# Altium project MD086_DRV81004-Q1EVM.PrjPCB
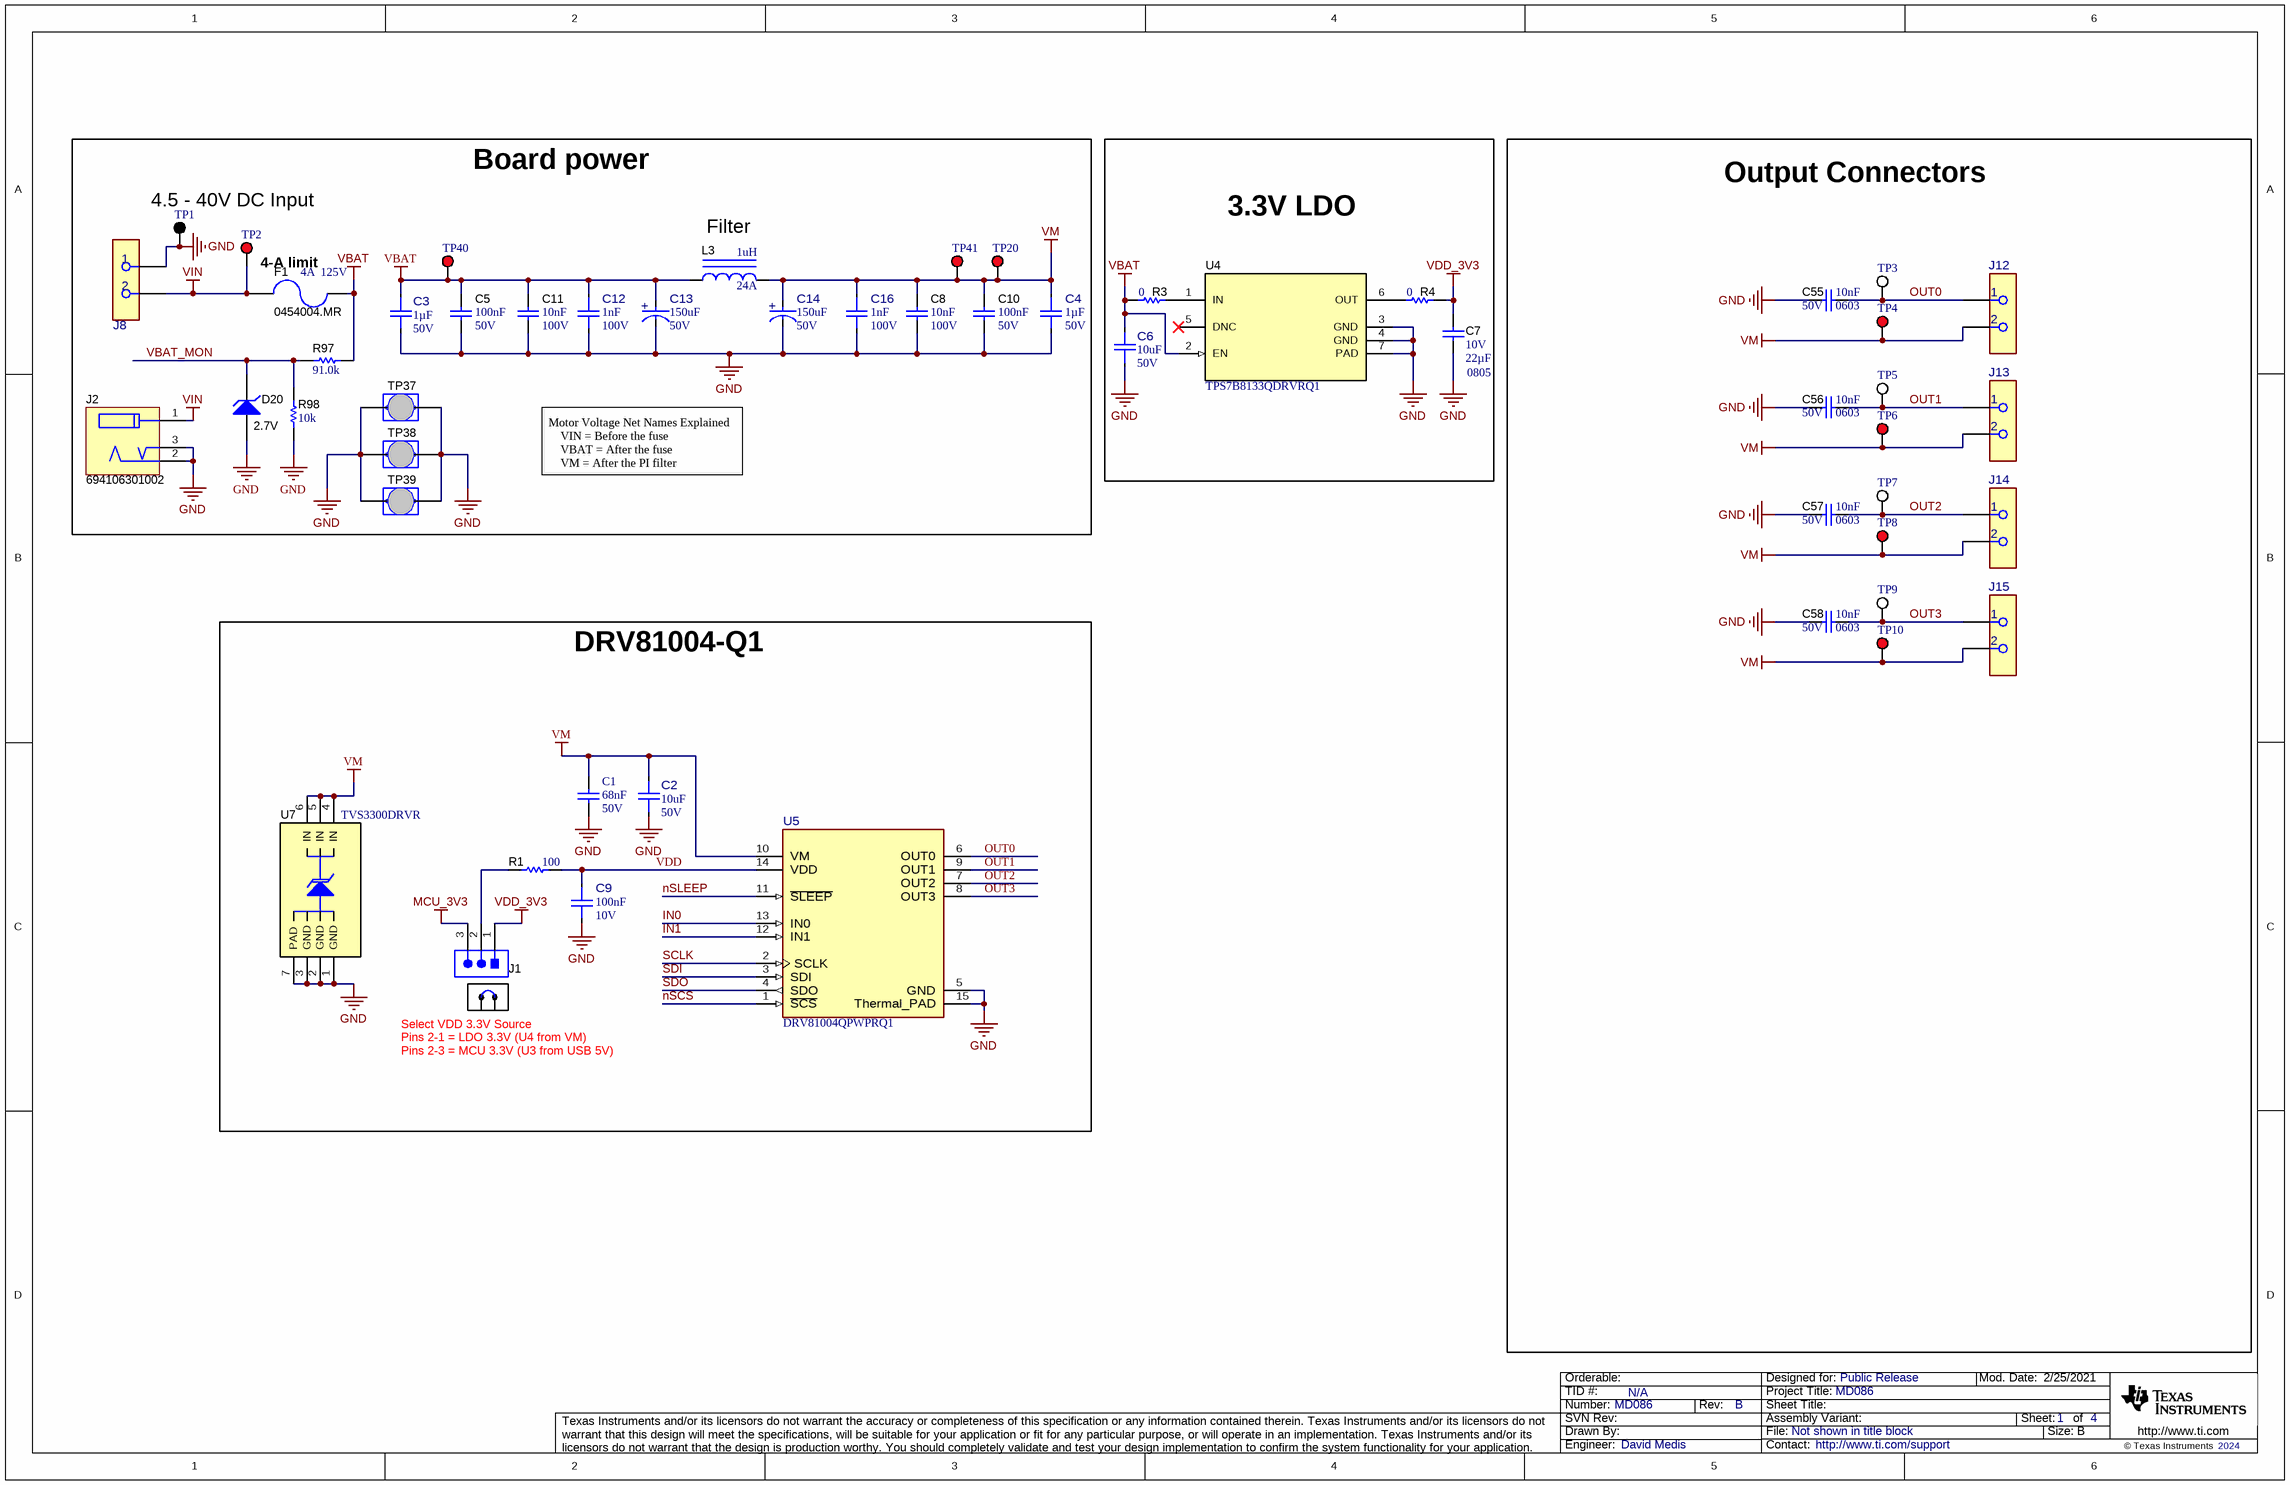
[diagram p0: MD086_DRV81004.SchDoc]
TID: N/A; TechSupport: http://www.ti.com/support; SCH_Rev: B; PRJ_Title: MD086; PRJ_Num_and_Rev: MD086B; PRJ_Number: MD086; PRJ_Engineer: David Medis; PRJ_Customer: Public Release; PCB_Rev: B; PCB_Layout: Jacob Thompson; DRV_PartNumber: DRV81004-Q1; DRV_EVM_Orderable: DRV81004-Q1EVM; CopyrightYear: 2024
4 sheets, 217 parts. Net scope: global (net labels, ports and power ports of the same name join across sheets).
Board file: DRV81004-Q1EVM.PcbDoc
Sheets:
  MD086_DRV81004.SchDoc
  MD086_ezFET.SchDoc
  MD086_MCU.SchDoc
  MD086_Hardware.SchDoc

## Sheet MD086_DRV81004.SchDoc
size 431 x 279 mm; Date: Not shown in title block; ApprovedBy: Not shown in title block; CheckedBy: Not shown in title block; Author: Not shown in title block; CompanyName: Not shown in title block; DrawnBy: David Medis; Engineer: Not shown in title block; Organization: Not shown in title block; Address1: Not shown in title block; Address2: Not shown in title block; Address3: Not shown in title block; Address4: Not shown in title block; DocumentNumber: 1; Revision: Use project parameter SCH_Rev; SheetNumber: 1; SheetTotal: 4; PageSetup: Record=PageOptions¦CenterHorizontal=True¦CenterVertical=True¦PrintScale=1.00¦XCorrection=1.00¦YCorrection=1.00¦PrintKind=0¦BorderSize=5000000¦LeftOffset=0¦BottomOffset=0¦Orientation=2¦PaperLength=1000¦PaperWidth=1000¦Scale=100¦PaperSource=15¦PrintQuality=600¦MediaType=1¦DitherType=10¦PaperKind=Letter¦PrintScaleMode=1

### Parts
C1  Cap_F: 68nF  Rated Voltage (DC): 50V  [WCAP-CSGP_0603_L1.6W0.8H0.8_Reflow]  (hidden comment: 885012206094)
C2  ValueDisplayed: 10uF  VDC_V: 50V  [FP-885012209073_1210-MFG]  (hidden comment: 885012209073)
C3  Cap_F: 1µF  VDC_V: 50V  [FP-885012206126_0603-MFG]  (hidden comment: 885012206126)
C4  Cap_F: 1µF  VDC_V: 50V  [FP-885012206126_0603-MFG]  (hidden comment: 885012206126)
C5  Cap_F: 100nF  VDC_V: 50V  [0603]  (hidden comment: 885012206095)
C6  ValueDisplayed: 10uF  VDC_V: 50V  [FP-885012209073_1210-MFG]  (hidden comment: 885012209073)
C7  PackageReference: 0805  VDC_V: 10V  ValueDisplayed: 22µF  [0805_150]  (hidden comment: 885012107011)
C8  Value2: 100V  Cap_F: 10nF  [0603]  (hidden comment: 885012206114)
C9  value 100nF  VDC_V: 10V  [FP-885012205018_0402-MFG]  (hidden comment: 885012205018)
C10  Cap_F: 100nF  VDC_V: 50V  [0603]  (hidden comment: 885012206095)
C11  Value2: 100V  Cap_F: 10nF  [0603]  (hidden comment: 885012206114)
C12  ValueDisplayed: 1nF  VDC_V: 100V  [FP-885012006085_0603-MFG]  (hidden comment: 885012006085)
C13  VDC_V: 50V  ValueDisplayed: 150uF  [FP-865080657017_RADIAL-MFG]  (hidden comment: 865080657017)
C14  VDC_V: 50V  ValueDisplayed: 150uF  [FP-865080657017_RADIAL-MFG]  (hidden comment: 865080657017)
C16  ValueDisplayed: 1nF  VDC_V: 100V  [FP-885012006085_0603-MFG]  (hidden comment: 885012006085)
C55  VDC_V: 50V  Cap_F: 10nF  [0603]  (hidden comment: 885012206089)
C56  VDC_V: 50V  Cap_F: 10nF  [0603]  (hidden comment: 885012206089)
C57  VDC_V: 50V  Cap_F: 10nF  [0603]  (hidden comment: 885012206089)
C58  VDC_V: 50V  Cap_F: 10nF  [0603]  (hidden comment: 885012206089)
D20  value 2.7V  [SOD-123]  (hidden comment: MMSZ4682-E3-08)
F1  0454004.MR  Irating_A: 4A  VDC_V: 125V  [SloBlo452]
J1  61300311121  [WURTH_61300311121]  (value not drawn)
J2  694106301002  [Wurth_694106301002]
J8  691250610002  [FP-691250610002_CONN_TERM_BLOCK2-MFG]  (value not drawn)
J12  691101710002  [FP-691101710002_TERM_BLK_2-MFG]  (value not drawn)
J13  691101710002  [FP-691101710002_TERM_BLK_2-MFG]  (value not drawn)
J14  691101710002  [FP-691101710002_TERM_BLK_2-MFG]  (value not drawn)
J15  691101710002  [FP-691101710002_TERM_BLK_2-MFG]  (value not drawn)
L3  Imax_A: 24A  ValueDisplayed: 1uH  [WE-HCC_1210]  (hidden comment: 7443320100)
R1  ValueDisplayed: 100  [0402S]  (hidden comment: RC0402FR-07100RL)
R3  value 0  [0603L]  (hidden comment: Resistor)
R4  value 0  [0603L]  (hidden comment: Resistor)
R97  ValueDisplayed: 91.0k  [0603L]  (hidden comment: RG1608P-913-B-T5)
R98  ValueDisplayed: 10k  [0603L]  (hidden comment: RC0603JR-0710KL)
SH-J34  60900213421  [Wurth_60900213421]  (value not drawn)
TP1  5011  [Keystone5011]  (value not drawn)
TP2  5010  [Keystone5010]  (value not drawn)
TP3  5012  [Keystone5012]  (value not drawn)
TP4  5010  [Keystone5010]  (value not drawn)
TP5  5012  [Keystone5012]  (value not drawn)
TP6  5010  [Keystone5010]  (value not drawn)
TP7  5012  [Keystone5012]  (value not drawn)
TP8  5010  [Keystone5010]  (value not drawn)
TP9  5012  [Keystone5012]  (value not drawn)
TP10  5010  [Keystone5010]  (value not drawn)
TP20  5010  [Keystone5010]  (value not drawn)
TP37  Jumper_2p  [Harwin_D3082-05]  (value not drawn)
TP38  Jumper_2p  [Harwin_D3082-05]  (value not drawn)
TP39  Jumper_2p  [Harwin_D3082-05]  (value not drawn)
TP40  5010  [Keystone5010]  (value not drawn)
TP41  5010  [Keystone5010]  (value not drawn)
U4  TPS7B8133QDRVRQ1  [DRV0006A]
U5  DRV81004QPWPRQ1  [PWP0014L-MFG]
U7  TVS3300DRVR  [DRV0006A]

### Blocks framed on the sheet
Board power: C3-C5 C8 C10-C14 C16 D20 F1 J2 J8 L3 R97 R98 TP1 TP2 TP20 TP37-TP41
3.3V LDO: C6 C7 R3 R4 U4
Output Connectors: C55-C58 J12-J15 TP3-TP10

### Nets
GND: C1.1 C2.1 C3.2 C4.2 C5.2 C6.1 C7.2 C8.1 C9.2 C10.2 C11.1 C12.2 C13.1(CATHODE) C14.1(CATHODE) C16.2 C55.1 C56.1 C57.1 C58.1 D20.2(A) J2.2 J2.3 J8.1 R98.2 TP1.1 TP37.1 TP37.2 TP38.1 TP38.2 TP39.1 TP39.2 U4.3(GND) U4.4(GND) U4.7(PAD) U5.5(GND) U5.15(Thermal_PAD) U7.1(GND) U7.2(GND) U7.3(GND) U7.7(PAD)
MCU_3V3: J1.3
VBAT: C3.1 C5.1 C6.2 C11.2 C12.1 C13.2(ANODE) F1.1 L3.1 R3.2 R97.2 TP40.1 U4.2(EN)
VDD_3V3: C7.1 J1.1 R4.1
VIN: F1.2 J2.1 J8.2 TP2.1
VM: C1.2 C2.2 C4.1 C8.2 C10.1 C14.2(ANODE) C16.1 J12.2 J13.2 J14.2 J15.2 L3.2 TP4.1 TP6.1 TP8.1 TP10.1 TP20.1 TP41.1 U5.10(VM) U7.4(IN) U7.5(IN) U7.6(IN)
IN0: U5.13(IN0)
IN1: U5.12(IN1)
nSCS: U5.1(~{SCS})
nSLEEP: U5.11(~{SLEEP})
OUT0: C55.2 J12.1 TP3.1 U5.6(OUT0)
OUT1: C56.2 J13.1 TP5.1 U5.9(OUT1)
OUT2: C57.2 J14.1 TP7.1 U5.7(OUT2)
OUT3: C58.2 J15.1 TP9.1 U5.8(OUT3)
SCLK: U5.2(SCLK)
SDI: U5.3(SDI)
SDO: U5.4(SDO)
VBAT_MON: D20.1(K) R97.1 R98.1
VDD: C9.1 R1.1 U5.14(VDD)
NetJ1_2: J1.2 R1.2
NetR3_1: R3.1 U4.1(IN)
NetR4_2: R4.2 U4.6(OUT)

Not connected (* = marked no-connect by the designer): U4 5(DNC)*

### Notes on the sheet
- (near TP1) 4.5 - 40V DC Input
- (near L3) Filter
- 4-A limit
- Motor Voltage Net Names Explained
  VIN = Before the fuse
  VBAT = After the fuse
  VM = After the PI filter
- (near SH-J34) Select VDD 3.3V Source
- (near SH-J34) Pins 2-1 = LDO 3.3V (U4 from VM)
- (near SH-J34) Pins 2-3 = MCU 3.3V (U3 from USB 5V)

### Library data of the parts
C1 = CMP-0111903-1: 68 nF ±10% 50V Ceramic Capacitor X7R 0603; Manufacturer: Wurth Elektronik; Capacitance Tolerance: +/-10%; Dissipation Factor: 3%; Insulation Resistance: 7.4GOhm; Match Code: WCAP-CSGP; Technical Reference: X7R0603683K050DFCT10000; Value: 68nF
C2 C6 = CMP-0097489-1: 10 µF ±10% 50V Ceramic Capacitor X7R 1210 (3225 Metric); Manufacturer: Wurth Electronics; SizeZ_mm: 2.8mm; AEC Qualified: No; Value: 10µF; TempCo: 15%
C3 C4 = CMP-0120896-1: 1 µF ±10% 50V Ceramic Capacitor X7R 0603 (1608 Metric); Manufacturer: Wurth Electronics; AEC Qualified: No; SizeZ_mm: 0.95mm; TempCo: 15%; ValueDisplayed: 1uF; Value: 1µF
C5 C10 = CMP-0006837-4: CAP, CERM, 0.1 uF, 50 V, +/- 10%, X7R, 0603; Manufacturer: Wurth Elektronik; TaMin_C: -55°C; Polarized: N; SizeAreaWB_mm2: 4.68; Value1: Unknown; U/M: EA; Value: 0.1uF; TaMax_C: 125°C; SizeZ_mm: 1; SizeX_mm: 1.6; SizeY_mm: 0.8; SizeArea_mm2: 1.28; AEC Category: Q200
C7 = CMP-0078153-1: CAP, CERM, 22 µF, 10 V,+/- 20%, X5R, 0805; Manufacturer: Wurth Elektronik; TaMin_C: -55°C; Polarized: N; SizeAreaWB_mm2: 6.75; U/M: EA; Value: 22uF; TaMax_C: 85°C; SizeZ_mm: 1.5; SizeX_mm: 2; SizeY_mm: 1.25; SizeArea_mm2: 2.5; AEC Category: Q200
C8 C11 = CMP-0079993-1: CAP, CERM, 0.01 µF, 100 V,+/- 10%, X7R, 0603; Manufacturer: Wurth Elektronik; TaMin_C: -55°C; Polarized: N; SizeAreaWB_mm2: 4.68; U/M: EA; Value: 0.01uF; TaMax_C: 105°C; SizeZ_mm: 1; SizeX_mm: 1.6; SizeY_mm: 0.8; SizeArea_mm2: 1.28; AEC Category: Q200; ValueDisplayed: 0.01µF
C9 = CMP-0090362-1: 0.1µF ±10% 10V Ceramic Capacitor X7R 0402 (1005 Metric); Manufacturer: Wurth Electronics; AEC Qualified: No; SizeZ_mm: 0.55mm; ValueDisplayed: 100000pF; TempCo: 15%
C12 C16 = CMP-0097311-1: 1000 pF ±5% 100V Ceramic Capacitor C0G, NP0 0603 (1608 Metric); Manufacturer: Wurth Electronics; TempCo: 30ppm/°C; SizeZ_mm: 0.87mm; AEC Qualified: No; Value: 1nF
C13 C14 = CMP-0097488-1: 150 µF 50 V Aluminum Electrolytic Capacitors Radial, Can - SMD 2000 Hrs @ 105°C; Manufacturer: Wurth Electronics; Cap_F: 150µF; Life: 2000Hours; IRMS_A: 600mA; Dissipation Factor: 12%; Value: 150µF; Leakage Current: 75uA; Tolerance_%: 20%; AEC Qualified: No; SizeZ_mm: 10.5mm
C55-C58 = CMP-0750039-1: CAP, CERM, 0.01 µF, 50 V,+/- 10%, X7R, 0603; Manufacturer: Wurth Elektronik; Polarized: N; AEC Category: Q200; TaMax_C: 125°C; SizeAreaWB_mm2: 4.68; Value: 0.01uF; SizeArea_mm2: 1.28; SizeY_mm: 0.8; SizeZ_mm: 1; ValueDisplayed: 0.01µF; SizeX_mm: 1.6; U/M: EA; TaMin_C: -55°C
D20 = CMP-0077592-3: Diode, Zener, 2.7 V, 500 mW, SOD-123; Manufacturer: Vishay-Semiconductor; AEC Category: Q101; AEC Qualified: N; SizeAreaWB_mm2: 13.095; SizeY_mm: 1.7; SizeX_mm: 3.85; Value1: 0.5W; SizeArea_mm2: 6.545; SizeZ_mm: 1.35; RJA_CperW: 340; Power_W: 500mW
F1 = CMP-0003486-2: Fuse, 4 A, 125VAC/VDC, SMD; Manufacturer: Littelfuse; MeltingTyp: 34.4; Rtyp_Ohm: 0.0186; Interrupt_AC: 50A; Value: 4A / 125V
J1 = CMP-0054796-4: Header, 2.54 mm, 3x1, Gold, TH; Manufacturer: Wurth Elektronik; Green_Lifecycle: Active; Green_REACh: Passed; CT: FALSE; CNHeader: TRUE
J2 = CMP-0054778-4: WR-DC DC Power Jack, R/A, TH; Manufacturer: Wurth Elektronik; Gender: Male
J8 = CMP-0093233-2: 2 Position Wire to Board Terminal Block Horizontal with Board 0.250" (6.35mm) Through Hole; Manufacturer: Wurth Electronics; Current_A: 32A; Conn Gender: Female; Row_Count: 1; ContactFinish: Zinc; SizeZ_mm: 21.6mm; Max Wire Gauge: 10; Min Wire Gauge: 30; Voltage_V: 450V; AEC Qualified: No; Is Female: yes
J12-J15 = CMP-0121353-1: 2 Position Wire to Board Terminal Block Horizontal with Board 0.197" (5.00mm) Through Hole; Manufacturer: Wurth; Current_A: 16A; Row_Count: 1; Voltage_V: 250V; AEC Qualified: No; Conn Gender: Female; DUT-Pitch_mm: 5mm; Is Female: yes; Max Wire Gauge: 14; Min Wire Gauge: 26; SizeZ_mm: 12.8mm
L3 = CMP-0063986-1: Inductor, Shielded Drum Core, Ferrite, 1 uH, 24 A, 0.0012 ohm, SMD; Manufacturer: Wurth Elektronik; Isat: 32A @ 30% inductance drop; Irms: 24A @ 50C rise; Green_Lifecycle: Active; SizeAreaWB_mm2: 188.94; DCR_ohm: 1.2m; Green_REACh: Passed; Value: 1uH; SizeZ_mm: 10; SizeX_mm: 12.1; SizeY_mm: 11.4; SizeArea_mm2: 137.94; Ind_H: 1µH; AEC Category: Q200
R1 = CMP-0026722-1: RES, 100, 1%, 0.063 W, 0402; Manufacturer: Yageo America; Power_W: 63mW; TempCo: 100 ppm/C; Value_Code: 100R; U/M: EA; Value: 100; EIA_Code: E96; SizeX_mm: 1; SizeY_mm: 0.5; SizeZ_mm: 0.6; Value2: 0.063W; AEC Qualified: N; VDC_V: 50V; AEC Category: Q200
R3 R4 = CMP-0025697-4: RES, 0, 5%, 0.1 W, AEC-Q200 Grade 0, 0603; PartNumber: CRCW06030000Z0EA; Manufacturer: Vishay-Dale; Value_Code: 0000; Power_W: 100mW; Value2: 0.1W; VDC_V: 75V; TempCo: 200 ppm/C; EIA_Code: E24; AEC Category: Q200; AEC Qualified: Y; SizeArea_mm2: 1.28; SizeX_mm: 1.6; SizeY_mm: 0.8; SizeZ_mm: 1
R97 = CMP-0023620-3: RES, 91.0 k, 0.1%, 0.1 W, 0603; Manufacturer: Susumu Co Ltd; Power_W: 100mW; TempCo: 25 ppm/C; Value_Code: 91k0; U/M: EA; Value: 91.0k; Res_ohm: 91k; SizeX_mm: 1.6; SizeY_mm: 0.8; SizeZ_mm: 1; Value2: 0.1W; SizeArea_mm2: 1.28; VDC_V: 75V; AEC Category: Q200
R98 = CMP-0025886-5: RES, 10 k, 5%, 0.1 W, 0603; Manufacturer: Yageo; Power_W: 100mW; TempCo: 100 ppm/C; Value_Code: 10k0; Value: 10k; EIA_Code: E24; SizeX_mm: 1.6; SizeY_mm: 0.8; SizeZ_mm: 1; Value2: 0.1W; SizeArea_mm2: 1.28; AEC Qualified: N; VDC_V: 75V; AEC Category: Q200; SizeAreaWB_mm2: 4.68
SH-J34 = CMP-0003761-2: Shunt, 2.54mm, Gold, Black; Manufacturer: Wurth Elektronik
TP1 = CMP-0055148-2: Test Point, Multipurpose, Black, TH; Manufacturer: Keystone Electronics; CNHeader: FALSE; Green_Lifecycle: Active; Green_REACh: Passed; ContactFinish: Silver; CT: TRUE
TP2 TP4 TP6 TP8 TP10 TP20 TP40 TP41 = CMP-0055147-2: Test Point, Multipurpose, Red, TH; Manufacturer: Keystone Electronics; CNHeader: FALSE; Green_Lifecycle: Active; Green_REACh: Passed; ContactFinish: Silver; CT: TRUE
TP3 TP5 TP7 TP9 = CMP-0055149-2: Test Point, Multipurpose, White, TH; Manufacturer: Keystone Electronics; ContactFinish: Silver; CT: TRUE; CNHeader: FALSE; Green_Lifecycle: Active; Green_REACh: Passed
TP37-TP39 = CMP-0075110-1: 1mm Uninsulated Shorting Plug, 10.16mm spacing, TH; Manufacturer: Harwin; PartNumber: D3082-05; CompType: Jumper Wire; CNHeader: False; Green_Lifecycle: Active; Green_REACh: Passed
U4 = CMP-0860463-2: Automotive 150-mA high-voltage ultra-low-IQ low-dropout (LDO) linear regulator, DRV0006A (WSON-6); Alternate Manufacturer: Texas Instruments; AEC Qualified: Y; SizeY_mm: 2; SizeZ_mm: 0.8; AEC Category: Q200; CompType: IC; SizeArea_mm2: 4; SizeAreaWB_mm2: 9
U5 = CMP-0122274-1: 4-channel Low-side Driver for Automotive Relay Control; Manufacturer: Texas Instruments; SizeZ_mm: 1.2mm; AEC Qualified: Yes; AEC Grade: Grade 1; Max Supply Voltage: 40V; Min Supply Voltage: 3V; Nominal Supply Current: 1.75-2.8mA; Number Of Drivers: 4; Standoff Height: 0.05mm; TaMax_C: +125°C; TaMin_C: -40°C; TJmax_C: +150°C; Turn Off Delay Time: 8us; Turn On Delay Time: 4us
U7 = CMP-0013424-7: 33-V Precision Surge Protection Clamp, DRV0006A (WSON-6); Manufacturer: Texas Instruments; SizeX_mm: 2; CompType: IC; SizeZ_mm: 0.8; SizeArea_mm2: 4; SizeAreaWB_mm2: 9; U/M: EA

## Sheet MD086_ezFET.SchDoc
size 431 x 279 mm; Date: Not shown in title block; ApprovedBy: Not shown in title block; CheckedBy: Not shown in title block; Author: Not shown in title block; CompanyName: Not shown in title block; DrawnBy: Murugavel Raju; Engineer: Not shown in title block; Organization: Not shown in title block; Address1: Not shown in title block; Address2: Not shown in title block; Address3: Not shown in title block; Address4: Not shown in title block; DocumentNumber: 3; Revision: Use project parameter SCH_Rev; SheetNumber: 3; SheetTotal: 4; PageSetup: Record=PageOptions¦CenterHorizontal=True¦CenterVertical=True¦PrintScale=1.00¦XCorrection=1.00¦YCorrection=1.00¦PrintKind=0¦BorderSize=5000000¦LeftOffset=0¦BottomOffset=0¦Orientation=2¦PaperLength=1000¦PaperWidth=1000¦Scale=100¦PaperSource=15¦PrintQuality=600¦MediaType=1¦DitherType=10¦PaperKind=Letter¦PrintScaleMode=1
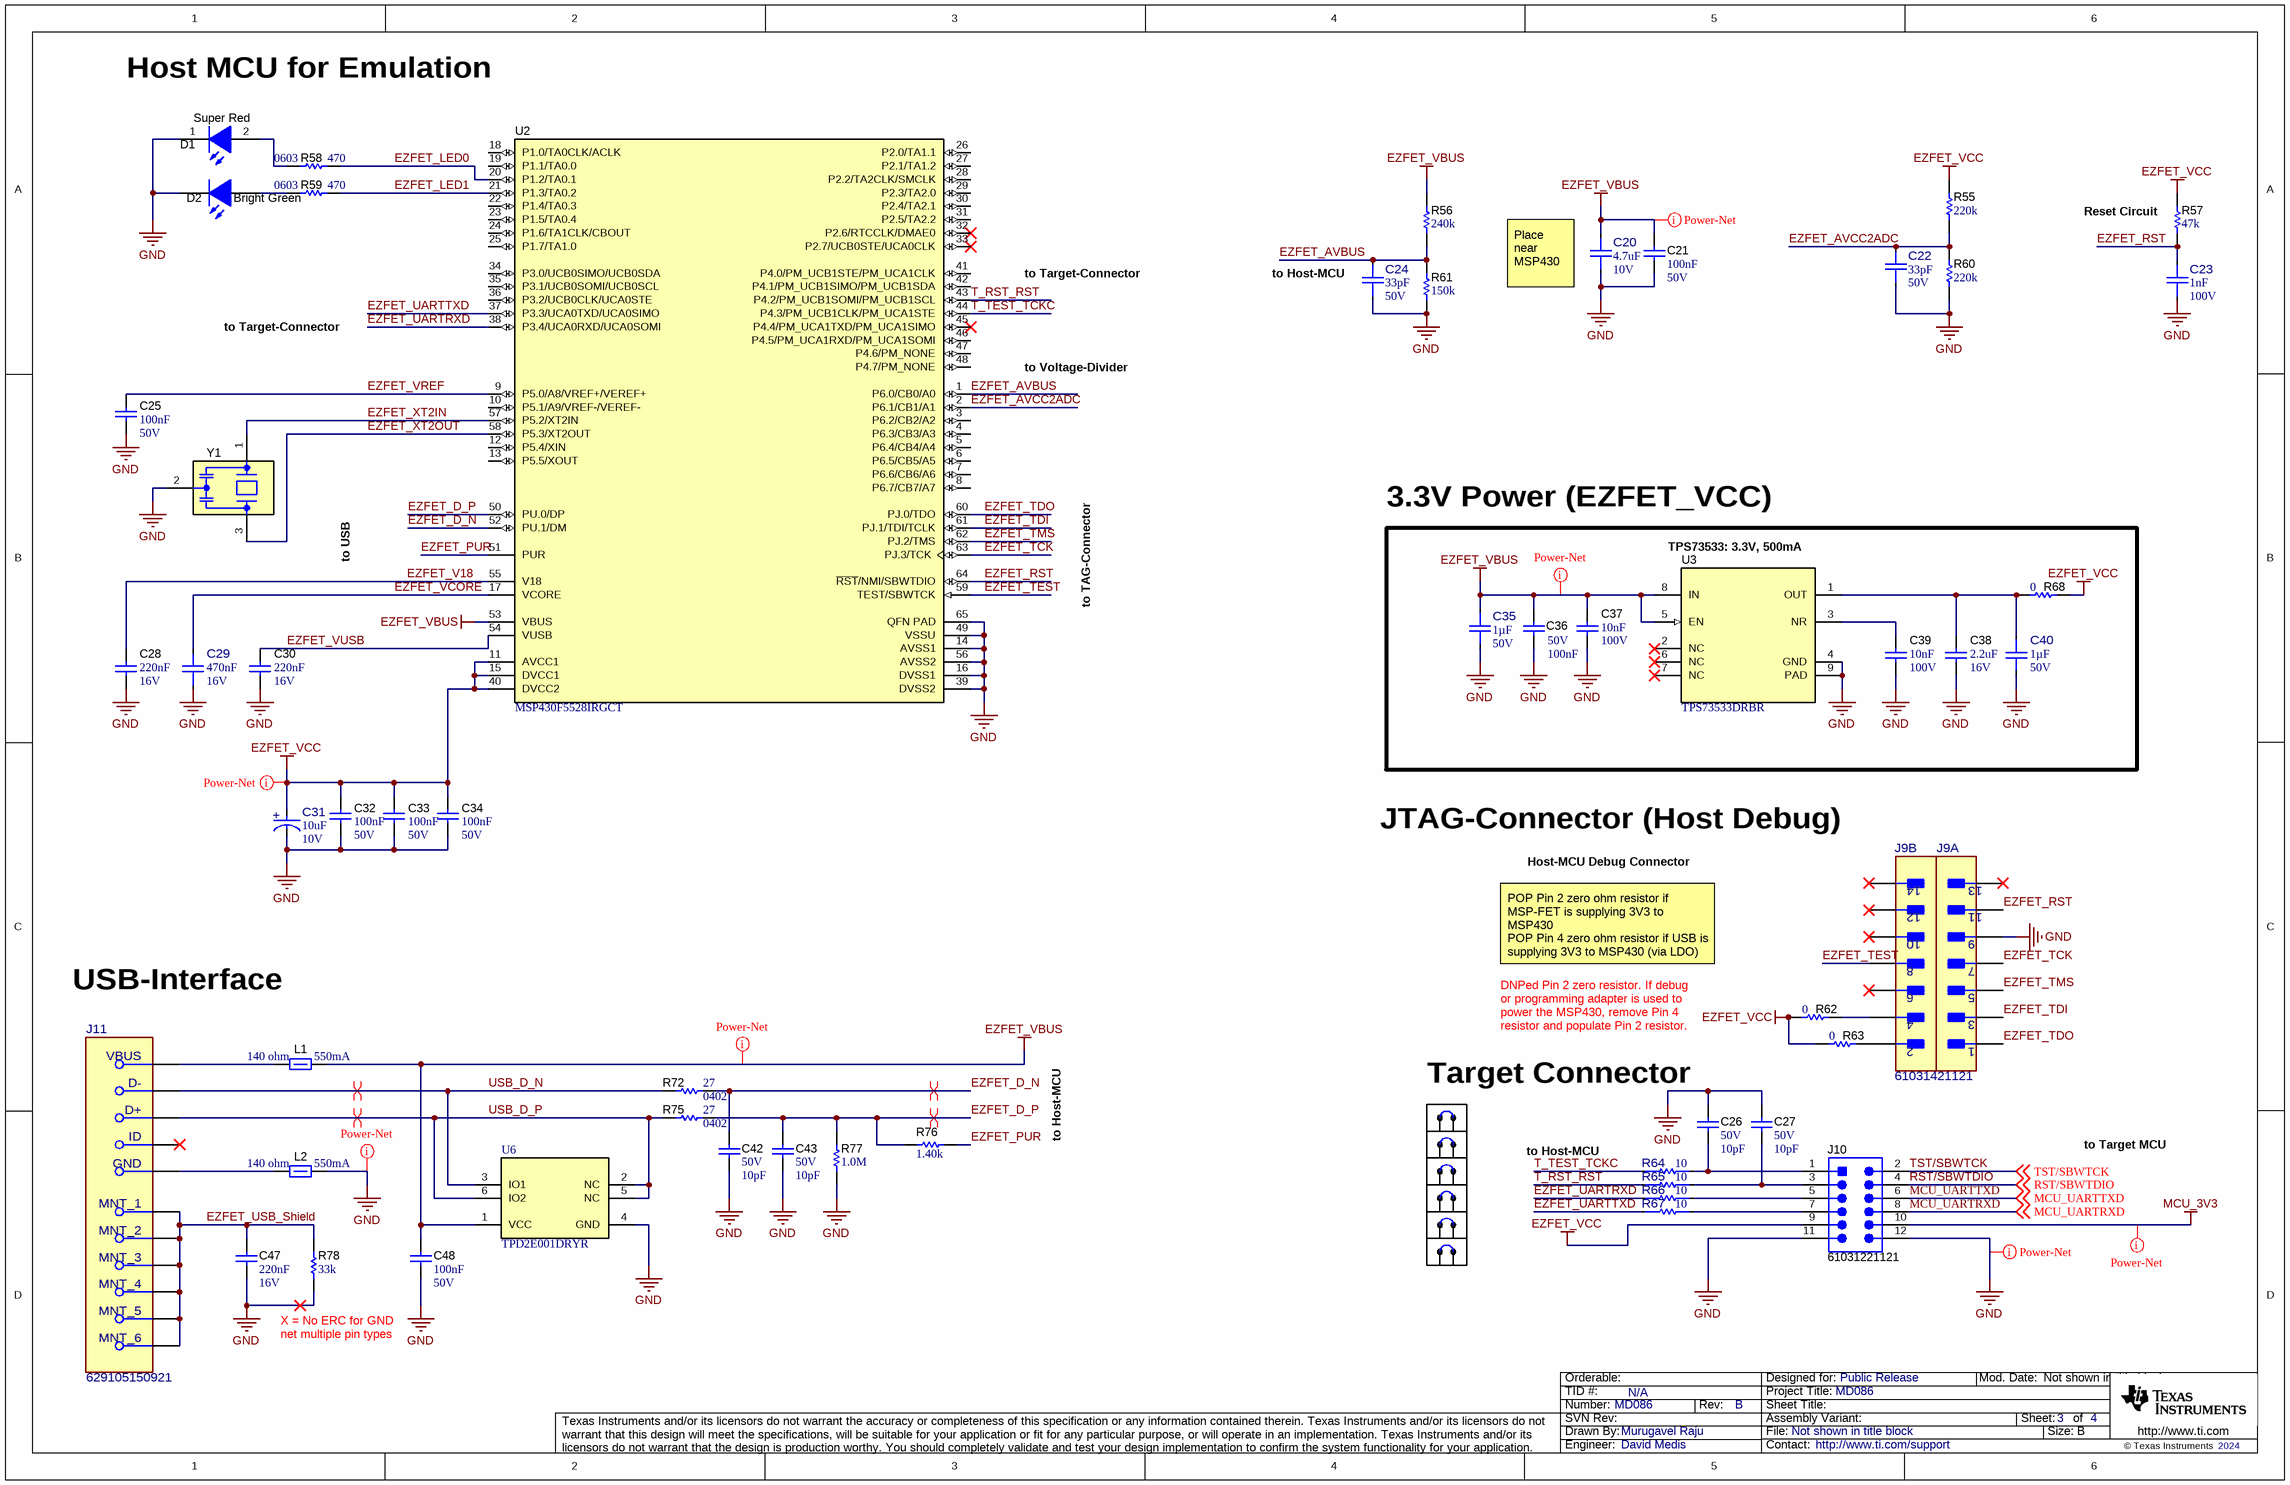
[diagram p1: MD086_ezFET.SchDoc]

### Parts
C20  ValueDisplayed: 4.7uF  VDC_V: 10V  [FP-885012106012_0603-MFG]  (hidden comment: 885012106012)
C21  Cap_F: 100nF  VDC_V: 50V  [0603]  (hidden comment: 885012206095)
C22  ValueDisplayed: 33pF  VDC_V: 50V  [FP-885012005058_0402-MFG]  (hidden comment: 885012005058)
C23  ValueDisplayed: 1nF  VDC_V: 100V  [FP-885012006085_0603-MFG]  (hidden comment: 885012006085)
C24  ValueDisplayed: 33pF  VDC_V: 50V  [FP-885012005058_0402-MFG]  (hidden comment: 885012005058)
C25  Cap_F: 100nF  VDC_V: 50V  [0603]  (hidden comment: 885012206095)
C26  VDC_V: 50V  ValueDisplayed: 10pF  [0402]  (hidden comment: 885012005055)
C27  VDC_V: 50V  ValueDisplayed: 10pF  [0402]  (hidden comment: 885012005055)
C28  Cap_F: 220nF  VDC_V: 16V  [0603L]  (hidden comment: 885012206048)
C29  VDC_V: 16V  Cap_F: 470nF  [FP-885012206050_0603-MFG]  (hidden comment: 885012206050)
C30  Cap_F: 220nF  VDC_V: 16V  [0603L]  (hidden comment: 885012206048)
C31  ValueDisplayed: 10uF  VDC_V: 10V  [FP-875105240001_SMT_CAP_4MM3_4MM3-MFG]  (hidden comment: 875105240001)
C32  Cap_F: 100nF  VDC_V: 50V  [0603]  (hidden comment: 885012206095)
C33  Cap_F: 100nF  VDC_V: 50V  [0603]  (hidden comment: 885012206095)
C34  Cap_F: 100nF  VDC_V: 50V  [0603]  (hidden comment: 885012206095)
C35  Cap_F: 1µF  VDC_V: 50V  [FP-885012206126_0603-MFG]  (hidden comment: 885012206126)
C36  Cap_F: 100nF  VDC_V: 50V  [0603]  (hidden comment: 885012206095)
C37  Value2: 100V  Cap_F: 10nF  [0603]  (hidden comment: 885012206114)
C38  VDC_V: 16V  ValueDisplayed: 2.2uF  [0603]  (hidden comment: 885012106018)
C39  Value2: 100V  Cap_F: 10nF  [0603]  (hidden comment: 885012206114)
C40  Cap_F: 1µF  VDC_V: 50V  [FP-885012206126_0603-MFG]  (hidden comment: 885012206126)
C42  VDC_V: 50V  ValueDisplayed: 10pF  [0402]  (hidden comment: 885012005055)
C43  VDC_V: 50V  ValueDisplayed: 10pF  [0402]  (hidden comment: 885012005055)
C47  Cap_F: 220nF  VDC_V: 16V  [0603L]  (hidden comment: 885012206048)
C48  Cap_F: 100nF  VDC_V: 50V  [0603]  (hidden comment: 885012206095)
D1  value Super Red  [WL-SMCW_RED]  (hidden comment: 150060SS75000)
D2  value Bright Green  [WL-SMCW_Green_0805]  (hidden comment: 150080VS75000)
J9  61031421121  [FP-61031421121_HDR14-MFG]  (value not drawn)  (parts A,B of 2)
J10  61031221121  [Wurth_61031221121]
J11  629105150921  [FP-629105150921_CONN_PTH_USB_8MM0_5MM6-MFG]
L1  value 140 ohm  Imax_A: 550mA  [0603L]  (hidden comment: 742792621)
L2  value 140 ohm  Imax_A: 550mA  [0603L]  (hidden comment: 742792621)
R55  ValueDisplayed: 220k  [0402]  (hidden comment: RC0402FR-07220KL)
R56  ValueDisplayed: 240k  [0402]  (hidden comment: CRCW0402240KFKED)
R57  ValueDisplayed: 47k  [0402]  (hidden comment: CRCW040247K0JNED)
R58  ValueDisplayed: 470  [0603]  (hidden comment: RC0603JR-07470RL)
R59  ValueDisplayed: 470  [0603]  (hidden comment: RC0603JR-07470RL)
R60  ValueDisplayed: 220k  [0402]  (hidden comment: RC0402FR-07220KL)
R61  ValueDisplayed: 150k  [0402]  (hidden comment: CRCW0402150KFKED)
R62  value 0  [0603L]  (hidden comment: Resistor)
R63  value 0  [0603L]  (hidden comment: Resistor)
R64  value 10  [FP-560050310009_0402-MFG]  (hidden comment: 560050310009)
R65  value 10  [FP-560050310009_0402-MFG]  (hidden comment: 560050310009)
R66  value 10  [FP-560050310009_0402-MFG]  (hidden comment: 560050310009)
R67  value 10  [FP-560050310009_0402-MFG]  (hidden comment: 560050310009)
R68  value 0  [0603L]  (hidden comment: Resistor)
R72  PackageReference: 0402  ValueDisplayed: 27  [0402L]  (hidden comment: CRCW040227R0JNED)
R75  PackageReference: 0402  ValueDisplayed: 27  [0402L]  (hidden comment: CRCW040227R0JNED)
R76  ValueDisplayed: 1.40k  [0402L]  (hidden comment: CRCW04021K40FKED)
R77  ValueDisplayed: 1.0M  [0402L]  (hidden comment: CRCW04021M00JNED)
R78  ValueDisplayed: 33k  [0402S]  (hidden comment: CRCW040233K0JNED)
SH-J27  60900213421  [Wurth_60900213421]  (value not drawn)
SH-J28  60900213421  [Wurth_60900213421]  (value not drawn)
SH-J31  60900213421  [Wurth_60900213421]  (value not drawn)
SH-J32  60900213421  [Wurth_60900213421]  (value not drawn)
SH-J33  60900213421  [Wurth_60900213421]  (value not drawn)
SH-J36  60900213421  [Wurth_60900213421]  (value not drawn)
U2  MSP430F5528IRGCT  [RGC0064B]
U3  TPS73533DRBR  [DRB0008A]
U6  TPD2E001DRYR  [DRY0006A]
Y1  CSTNR4M00GH5L000R0  [MuRata_CSTNR]  (value not drawn)

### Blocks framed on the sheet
3.3V Power (EZFET_VCC): C35-C40 R68 U3

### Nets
EZFET_VBUS: C20.2 C21.1 C35.1 C36.1 C37.1 C48.2 L1.2 R56.2 U2.53(VBUS) U3.5(EN) U3.8(IN) U6.1(VCC)
EZFET_VCC: C31.2(ANODE) C32.1 C33.1 C34.1 J10.9 R55.2 R57.2 R62.2 R63.2 R68.1 U2.11(AVCC1) U2.15(DVCC1) U2.40(DVCC2)
GND: C20.1 C21.2 C22.1 C23.1 C24.1 C25.2 C26.1 C27.1 C28.2 C29.1 C30.2 C31.1(CATHODE) C32.2 C33.2 C34.2 C35.2 C36.2 C37.2 C38.2 C39.2 C40.2 C42.2 C43.2 C47.2 C48.1 D1.1(K) D2.1(K) J9.9 J10.11 J10.12 L2.2 R60.1 R61.1 R77.1 R78.1 U2.14(AVSS1) U2.16(DVSS1) U2.39(DVSS2) U2.49(VSSU) U2.56(AVSS2) U2.65(QFN_PAD) U3.4(GND) U3.9(PAD) U6.4(GND) Y1.2(GND)
MCU_3V3: J10.10
EZFET_AVBUS: C24.2 R56.1 R61.2 U2.1(P6.0/CB0/A0)
EZFET_AVCC2ADC: C22.2 R55.1 R60.2 U2.2(P6.1/CB1/A1)
EZFET_D_N: C42.1 R72.2 U2.52(PU.1/DM)
EZFET_D_P: C43.1 R75.2 R76.1 R77.2 U2.50(PU.0/DP)
EZFET_LED0: R58.1 U2.20(P1.2/TA0.1)
EZFET_LED1: R59.1 U2.21(P1.3/TA0.2)
EZFET_PUR: R76.2 U2.51(PUR)
EZFET_RST: C23.2 J9.11 R57.1 U2.64(~{RST}/NMI/SBWTDIO)
EZFET_TCK: J9.7 U2.63(PJ.3/TCK)
EZFET_TDI: J9.3 U2.61(PJ.1/TDI/TCLK)
EZFET_TDO: J9.1 U2.60(PJ.0/TDO)
EZFET_TEST: J9.8 U2.59(TEST/SBWTCK)
EZFET_TMS: J9.5 U2.62(PJ.2/TMS)
EZFET_UARTRXD: R66.1 U2.38(P3.4/UCA0RXD/UCA0SOMI)
EZFET_UARTTXD: R67.1 U2.37(P3.3/UCA0TXD/UCA0SIMO)
EZFET_USB_Shield: C47.1 J11.6(MNT_1) J11.7(MNT_2) J11.8(MNT_3) J11.9(MNT_4) J11.10(MNT_5) J11.11(MNT_6) R78.2
EZFET_V18: C28.1 U2.55(V18)
EZFET_VCORE: C29.2 U2.17(VCORE)
EZFET_VREF: C25.1 U2.9(P5.0/A8/VREF+/VEREF+)
EZFET_VUSB: C30.1 U2.54(VUSB)
EZFET_XT2IN: U2.57(P5.2/XT2IN) Y1.1(In)
EZFET_XT2OUT: U2.58(P5.3/XT2OUT) Y1.3(Out)
MCU_UARTRXD: J10.8 ; off-sheet MCU_UARTRXD
MCU_UARTTXD: J10.6 ; off-sheet MCU_UARTTXD
RST/SBWTDIO: J10.4 ; off-sheet RST/SBWTDIO
T_RST_RST: R65.1 U2.43(P4.2/PM_UCB1SOMI/PM_UCB1SCL)
T_TEST_TCKC: R64.1 U2.44(P4.3/PM_UCB1CLK/PM_UCA1STE)
TST/SBWTCK: J10.2 ; off-sheet TST/SBWTCK
USB_D_N: J11.2(D-) R72.1 U6.3(IO1)
USB_D_P: J11.3(D+) R75.1 U6.2(NC) U6.5(NC) U6.6(IO2)
NetC26_2: C26.2 J10.1 R64.2
NetC27_2: C27.2 J10.3 R65.2
NetC38_1: C38.1 C40.1 R68.2 U3.1(OUT)
NetC39_1: C39.1 U3.3(NR)
NetD1_2: D1.2(A) R58.2
NetD2_2: D2.2(A) R59.2
NetJ9_2: J9.2 R63.1
NetJ9_4: J9.4 R62.1
NetJ10_5: J10.5 R66.2
NetJ10_7: J10.7 R67.2
NetJ11_1: J11.1(VBUS) L1.1
NetJ11_5: J11.5(GND) L2.1

Not connected (* = marked no-connect by the designer): J9 6* 10* 12* 13* 14*; J11 4(ID)*; U2 3(P6.2/CB2/A2) 4(P6.3/CB3/A3) 5(P6.4/CB4/A4) 6(P6.5/CB5/A5) 7(P6.6/CB6/A6) 8(P6.7/CB7/A7) 10(P5.1/A9/VREF-/VEREF-) 12(P5.4/XIN) 13(P5.5/XOUT) 18(P1.0/TA0CLK/ACLK) 19(P1.1/TA0.0) 22(P1.4/TA0.3) 23(P1.5/TA0.4) 24(P1.6/TA1CLK/CBOUT) 25(P1.7/TA1.0) 26(P2.0/TA1.1) 27(P2.1/TA1.2) 28(P2.2/TA2CLK/SMCLK) 29(P2.3/TA2.0) 30(P2.4/TA2.1) 31(P2.5/TA2.2) 32(P2.6/RTCCLK/DMAE0)* 33(P2.7/UCB0STE/UCA0CLK)* 34(P3.0/UCB0SIMO/UCB0SDA) 35(P3.1/UCB0SOMI/UCB0SCL) 36(P3.2/UCB0CLK/UCA0STE) 41(P4.0/PM_UCB1STE/PM_UCA1CLK) 42(P4.1/PM_UCB1SIMO/PM_UCB1SDA) 45(P4.4/PM_UCA1TXD/PM_UCA1SIMO)* 46(P4.5/PM_UCA1RXD/PM_UCA1SOMI) 47(P4.6/PM_NONE) 48(P4.7/PM_NONE); U3 2(NC)* 6(NC)* 7(NC)*

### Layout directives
net class Power-Net: EZFET_VBUS, EZFET_VCC, GND, MCU_3V3
differential pair: EZFET_D_N, EZFET_D_P, USB_D_N, USB_D_P

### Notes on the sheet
- Host MCU for Emulation
- (near R57) Reset Circuit
- to Target-Connector
- (near C24) to Host-MCU
- (near C20) Place near MSP430
- to Voltage-Divider
- to USB
- to TAG-Connector
- (near U3) TPS73533: 3.3V, 500mA
- JTAG-Connector (Host Debug)
- Host-MCU Debug Connector
- POP Pin 2 zero ohm resistor if MSP-FET is supplying 3V3 to MSP430
  POP Pin 4 zero ohm resistor if USB is supplying 3V3 to MSP430 (via LDO)
- USB-Interface
- to Host-MCU
- (near SH-J27) Target Connector
- DNPed Pin 2 zero resistor. If debug or programming adapter is used to power the MSP430, remove Pin 4 resistor and populate Pin 2 resistor.
- to Target MCU
- X = No ERC for GND net multiple pin types

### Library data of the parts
C20 = CMP-0097305-1: 4.7 µF ±20% 10V Ceramic Capacitor X5R 0603 (1608 Metric); Manufacturer: Wurth Electronics; Cap_F: 4.7µF; Value: 4.7µF; AEC Qualified: No; SizeZ_mm: 0.87mm; TempCo: 15%
C21 C25 C32-C34 C36 C48 = CMP-0006837-4: as C5 on sheet MD086_DRV81004
C22 C24 = CMP-0097306-1: 33 pF ±5% 50V Ceramic Capacitor C0G, NP0 0402 (1005 Metric); Manufacturer: Wurth Electronics; AEC Qualified: No; Value: 33pF; TempCo: 30ppm/°C; SizeZ_mm: 0.55mm
C23 = CMP-0097311-1: as C12 on sheet MD086_DRV81004
C26 C27 C42 C43 = CMP-0006215-2: CAP, CERM, 10 pF, 50 V, +/- 5%, C0G/NP0, 0402; Manufacturer: Wurth Elektronik; TaMin_C: -55°C; Polarized: N; SizeAreaWB_mm2: 3; Value1: Unknown; U/M: EA; Value: 10pF; TaMax_C: 125°C; SizeZ_mm: 0.6; SizeX_mm: 1; SizeY_mm: 0.5; AEC Category: Q200
C28 C30 C47 = CMP-0006830-4: CAP, CERM, 0.22 uF, 16 V, +/- 10%, X7R, 0603; Manufacturer: Wurth Elektronik; TaMin_C: -55°C; Polarized: N; SizeAreaWB_mm2: 4.68; Value1: Unknown; U/M: EA; Value: 0.22uF; TaMax_C: 125°C; SizeZ_mm: 1; SizeX_mm: 1.6; SizeY_mm: 0.8; Cap_Case: 0603; SizeArea_mm2: 1.28; AEC Category: Q200
C29 = CMP-0097608-1: 0.47 µF ±10% 16V Ceramic Capacitor X7R 0603 (1608 Metric); Manufacturer: Wurth Electronics; AEC Qualified: No; Value: 470nF; TempCo: 15%; SizeZ_mm: 0.87mm
C31 = CMP-0097340-1: Alum. Polymer Cap 10µF 10V 5.5mmV-Chip WCAP-PSLP Series Lifetime 2000h +105°C; Manufacturer: Wurth Electronics; Life: 2000Hours; Dissipation Factor: 8%; Esr: 45m; IRMS_A: 1.2A; Tolerance_%: 20%; AEC Qualified: No; SizeZ_mm: 5.5mm; Leakage Current: 300uA
C35 C40 = CMP-0120896-1: as C3 on sheet MD086_DRV81004
C37 C39 = CMP-0079993-1: as C8 on sheet MD086_DRV81004
C38 = CMP-0006825-5: CAP, CERM, 2.2 uF, 16 V, +/- 20%, X5R, 0603; Manufacturer: Wurth Elektronik; TaMin_C: -55°C; Polarized: N; SizeAreaWB_mm2: 4.68; Value1: Unknown; U/M: EA; Value: 2.2uF; TaMax_C: 85°C; SizeZ_mm: 1; SizeX_mm: 1.6; SizeY_mm: 0.8; SizeArea_mm2: 1.28; Cap_F: 2.2µF; AEC Category: Q200
D1 = CMP-0002893-1: LED, Super Red, SMD; Manufacturer: Wurth Elektronik; Io_A: 20mA; Value1: W; U/M: EA; Vf_V: 1.9V; Type: AlInGaP
D2 = CMP-0002960-2: LED, Bright Green, SMD; Manufacturer: Wurth Elektronik; Io_A: 20mA; Power_TotalModule: 72mW; Vr_V: 5V; Tjmax_C: 85°C; Value1: 0.072W; U/M: EA; Angle: 140; Vf_V: 2V; Type: AlInGaP
J9 = CMP-0122757-1: Connector Header Surface Mount 14 position 0.100" (2.54mm); Manufacturer: Wurth Electronics; ContactFinish: Gold; Current_A: 3A; Row_Count: 2; Voltage_V: 250V; AEC Qualified: No; Conn Gender: Male; Conn Orientation: Straight; SizeZ_mm: 9.9mm; Standoff Height: 0.76mm
J10 = CMP-0054791-2: Header, 2.54mm, 6x2, Gold, SMT; Manufacturer: Wurth Elektronik; Current_A: 3A; Shrouded: N; Gender: Male; Voltage_V: 250V; Row_Count: 2; RowSpacing_mm: 2.54
J11 = CMP-0097752-1: Conn Micro USB 2.0 Type AB RCP 5 POS 0.65mm Solder RA SMD 5 Terminal 1 Port T/R; Manufacturer: Wurth Electronics; Shrouded: true; Voltage_V: 30V; Usb Standard: USB 2.0; Current_A: 1A; ContactFinish: Gold; SizeZ_mm: 3.2mm; Is Female: yes; Conn Orientation: Horizontal; AEC Qualified: No
L1 L2 = CMP-0003184-2: Ferrite Bead, 140 ohm @ 100 MHz, 0.55 A, 0603; Manufacturer: Wurth Elektronik; Ztyp@1GHz_Ohm: 271.401; ZTyp@100MHz_Ohm: 140; SizeAreaWB_mm2: 4.68; DCR_ohm: 0.2; Value1: 0.2 ohm; SizeZ_mm: 1; SizeX_mm: 1.6; SizeY_mm: 0.8; Value2: 0.55A; SizeArea_mm2: 1.28
R55 R60 = CMP-0026728-1: RES, 220 k, 1%, 0.0625 W, 0402; Manufacturer: Yageo America; Power_W: 62.5mW; TempCo: 100 ppm/C; U/M: EA; Value: 220k; SizeX_mm: 1; SizeY_mm: 0.5; SizeZ_mm: 0.6; AEC Qualified: N; VDC_V: 50V; AEC Category: Q200
R56 = CMP-0026190-2: RES, 240 k, 1%, 0.063 W, AEC-Q200 Grade 0, 0402; Manufacturer: Vishay-Dale; Power_W: 63mW; TempCo: 100 ppm/C; Value: 240k; SizeX_mm: 1; SizeY_mm: 0.5; SizeZ_mm: 0.6; Value2: 0.063W; AEC Qualified: Y; VDC_V: 50V; AEC Category: Q200; AEC Grade: 0
R57 = CMP-0026935-3: RES, 47 k, 5%, 0.063 W, AEC-Q200 Grade 0, 0402; Manufacturer: Vishay-Dale; Power_W: 63mW; TempCo: 200 ppm/C; Value_Code: 47k0; Value: 47k; EIA_Code: E24; SizeX_mm: 1; SizeY_mm: 0.5; SizeZ_mm: 0.6; Value2: 0.063W; AEC Qualified: Y; VDC_V: 50V; AEC Category: Q200; AEC Grade: 0
R58 R59 = CMP-0025924-5: RES, 470, 5%, 0.1 W, 0603; Manufacturer: Yageo; Power_W: 100mW; TempCo: 100 ppm/C; Value_Code: 470R; Value: 470; EIA_Code: E24; SizeX_mm: 1.6; SizeY_mm: 0.8; SizeZ_mm: 1; Value2: 0.1W; SizeArea_mm2: 1.28; AEC Qualified: N; VDC_V: 75V; AEC Category: Q200; SizeAreaWB_mm2: 4.68
R61 = CMP-0026021-3: RES, 150 k, 1%, 0.063 W, AEC-Q200 Grade 0, 0402; Manufacturer: Vishay-Dale; Power_W: 63mW; TempCo: 100 ppm/C; Value: 150k; EIA_Code: E96; SizeX_mm: 1; SizeY_mm: 0.5; SizeZ_mm: 0.6; Value2: 0.063W; AEC Qualified: Y; VDC_V: 50V; AEC Category: Q200; AEC Grade: 0
R62 R63 R68 = CMP-0025697-4: as R3 on sheet MD086_DRV81004
R64-R67 = CMP-0097401-1: Thick Film Resistors 0402 10Ω ±1% 0.125W; Manufacturer: Wurth Electronics; TempCo: 100ppm/°C; VDC_V: 1.118V; Power_W: 125mW; AEC Qualified: No; SizeZ_mm: 0.4mm
R72 R75 = CMP-0026888-3: RES, 27, 5%, 0.063 W, AEC-Q200 Grade 0, 0402; Manufacturer: Vishay-Dale; Power_W: 63mW; TempCo: 200 ppm/C; Value_Code: 27R0; Value: 27; EIA_Code: E24; SizeX_mm: 1; SizeY_mm: 0.5; SizeZ_mm: 0.6; Value2: 0.063W; AEC Qualified: Y; VDC_V: 50V; AEC Category: Q200; AEC Grade: 0
R76 = CMP-0026085-3: RES, 1.40 k, 1%, 0.063 W, AEC-Q200 Grade 0, 0402; Manufacturer: Vishay-Dale; Power_W: 63mW; TempCo: 100 ppm/C; Value_Code: 1k40; Value: 1.40k; EIA_Code: E96; Res_ohm: 1.4k; SizeX_mm: 1; SizeY_mm: 0.5; SizeZ_mm: 0.6; Value2: 0.063W; AEC Qualified: Y; VDC_V: 50V; AEC Category: Q200; AEC Grade: 0
R77 = CMP-0026859-2: RES, 1.0 M, 5%, 0.063 W, AEC-Q200 Grade 0, 0402; Manufacturer: Vishay-Dale; Power_W: 63mW; TempCo: 200 ppm/C; Value_Code: 1M00; Value: 1.0Meg; EIA_Code: E24; Res_ohm: 1M; SizeX_mm: 1; SizeY_mm: 0.5; SizeZ_mm: 0.6; Value2: 0.063W; AEC Qualified: Y; VDC_V: 50V; AEC Category: Q200; AEC Grade: 0
R78 = CMP-0026907-3: RES, 33 k, 5%, 0.063 W, AEC-Q200 Grade 0, 0402; Manufacturer: Vishay-Dale; Power_W: 63mW; TempCo: 200 ppm/C; Value_Code: 33k0; Value: 33k; EIA_Code: E24; SizeX_mm: 1; SizeY_mm: 0.5; SizeZ_mm: 0.6; Value2: 0.063W; AEC Qualified: Y; VDC_V: 50V; AEC Category: Q200; AEC Grade: 0
SH-J27 SH-J28 SH-J31-SH-J33 SH-J36 = CMP-0003761-2: as SH-J34 on sheet MD086_DRV81004
U2 = CMP-0039269-4: 16-Bit Ultra-Low-Power Microcontroller, 128KB Flash, 8KB RAM, USB, 12Bit ADC, 2 USCIs, 32Bit HW MPY, RGC0064B (VQFN-64); Alternate Manufacturer: Texas Instruments; Alternate PartNumber: MSP430F5528IRGCR; ADC: 12-bit SAR; ADC Channels: 16; Brown Out Reset: Yes; DMA: 3; Flash(KB): 128; Frequency(MHz): 25; GPIO: 47; Multiplier: 32x32; SRAM(B): 8192; Timers - 16-bit: 4; USB: 1; USCI_A (UART/LIN/IrDA/SPI): 2; Rating: Catalog; SizeArea_mm2: 81.0; SizeZ_mm: 1.0; Green_REACh: Passed; AEC Qualified: N; AEC Category: Q200; CompType: IC; Green_Lifecycle: Active; SizeY_mm: 9.0; SizeAreaWB_mm2: 121.0
U3 = CMP-0036328-3: 500mA, Adjustable, Low Quiescent Current, Low-Noise, High-PSRR, Single-Output LDO Regulator, DRB0008A (VSON-8); Manufacturer: Texas Instruments; CompType: IC; Green_Lifecycle: Active; SizeZ_mm: 1.0; Iq(Typ)(mA): 0.04; SizeY_mm: 3.0; SizeAreaWB_mm2: 16.0; SizeArea_mm2: 9.0; AEC Category: Q200; Vout Adj(Max)(V): 3.3; AEC Qualified: N; Accuracy(%): 2; Vin(Max)(V): 6.5; Vdo(Typ)(mV): 280; Iout(Max)(A): 0.5; Green_REACh: Passed; Rating: Catalog; Vin(Min)(V): 2.7
U6 = CMP-0043099-3: Low-Capacitance 2-Channel +/-15kV ESD Protection Array for High-Speed Data Interfaces, DRY0006A (USON-6); Manufacturer: Texas Instruments; IO Leakage Current(nA): 1; IEC 61000-4-2 Air-Gap(+/- kV): 15; USB High Speed: TRUE; IO Capacitance(Typ)(pF): 1.5; Eco-Plan: Green (RoHS & no Sb/Br); Breakdown Voltage(Min)(V): 11; IEC 61000-4-2 Contact(+/- kV): 8; AEC Category: Q200; AEC Qualified: N; CompType: IC; SizeAreaWB_mm2: 4.9; SizeArea_mm2: 1.45; SizeX_mm: 1.0; SizeZ_mm: 0.6; Rating: Catalog
Y1 = CMP-0085483-1: Oscillator, 4 MHz, 700 ppm, 39 pF, SMD; Manufacturer: MuRata; SizeArea_mm2: 9; Load Capacitance: 39 pF; SizeZ_mm: 1.2; AEC Category: Q200; Frequency Tolerance: 700 ppm; SizeX_mm: 4.5; SizeAreaWB_mm2: 16.5; TaMax_C: 85°C; TaMin_C: -20°C; SizeY_mm: 2; AEC Qualified: N; Frequency_Fixed: 4MHz

## Sheet MD086_MCU.SchDoc
size 431 x 279 mm; Date: Not shown in title block; ApprovedBy: Not shown in title block; CheckedBy: Not shown in title block; Author: Not shown in title block; CompanyName: Not shown in title block; DrawnBy: David Medis; Engineer: Not shown in title block; Organization: Not shown in title block; Address1: Not shown in title block; Address2: Not shown in title block; Address3: Not shown in title block; Address4: Not shown in title block; DocumentNumber: 2; Revision: Use project parameter SCH_Rev; SheetNumber: 2; SheetTotal: 4; PageSetup: Record=PageOptions¦CenterHorizontal=True¦CenterVertical=True¦PrintScale=1.00¦XCorrection=1.00¦YCorrection=1.00¦PrintKind=0¦BorderSize=5000000¦LeftOffset=0¦BottomOffset=0¦Orientation=2¦PaperLength=1000¦PaperWidth=1000¦Scale=100¦PaperSource=15¦PrintQuality=600¦MediaType=1¦DitherType=10¦PaperKind=Letter¦PrintScaleMode=1
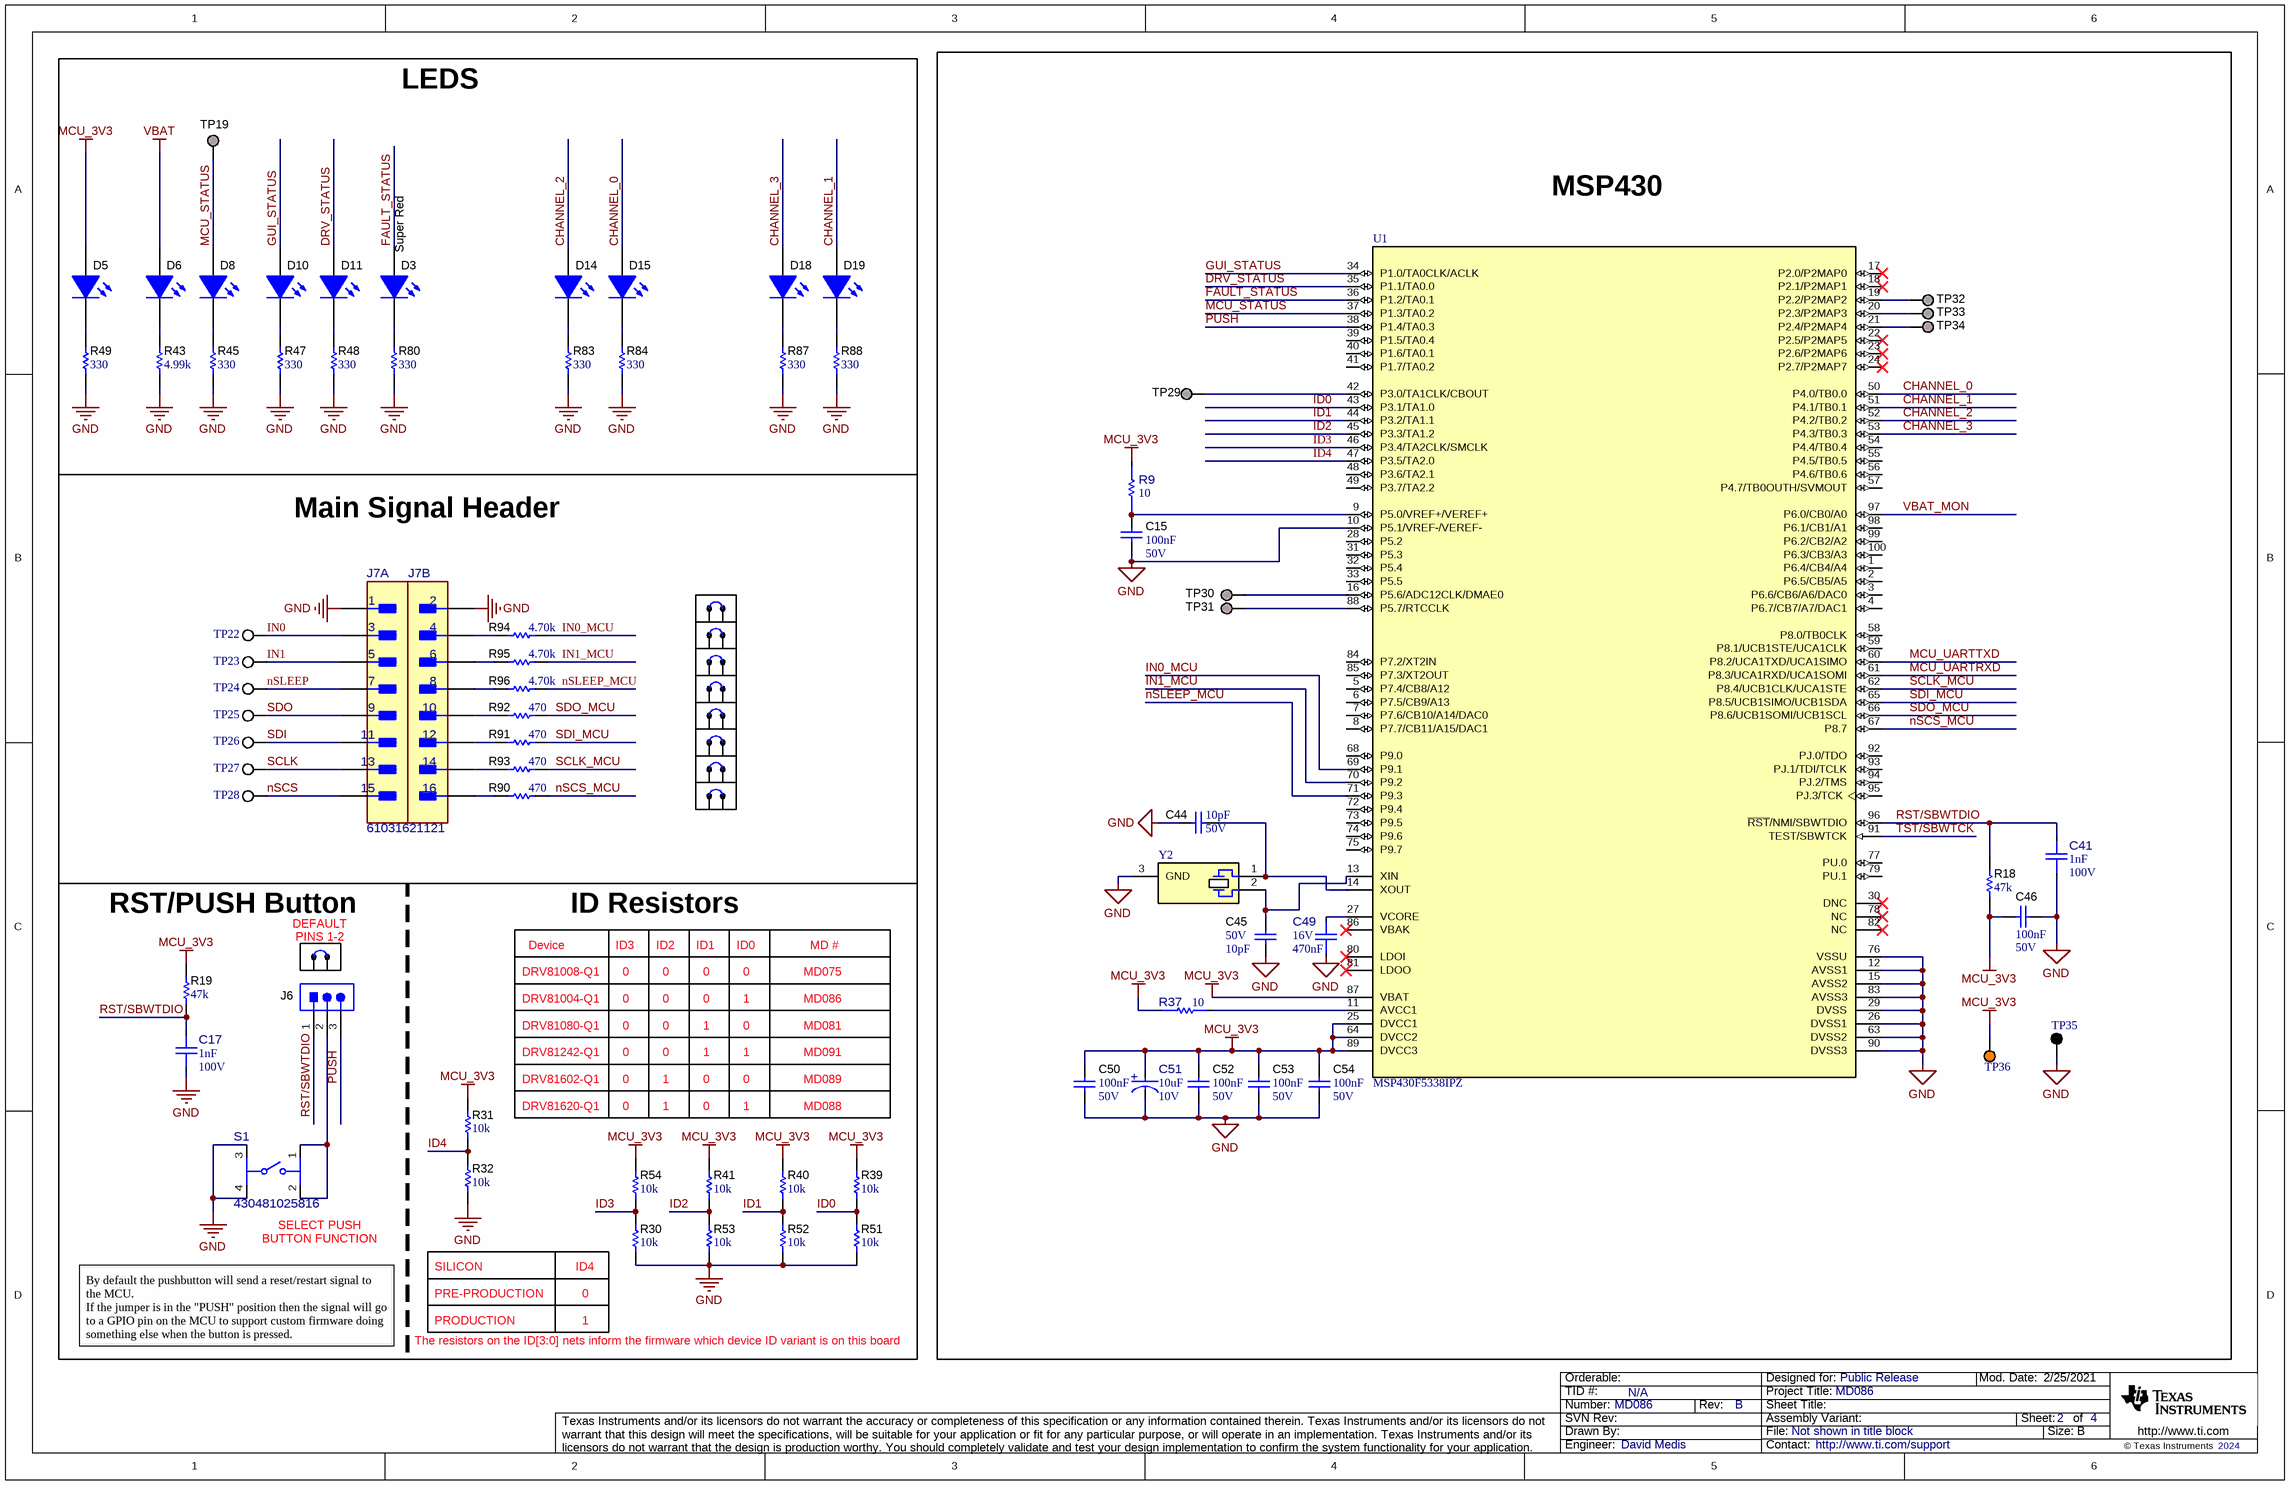
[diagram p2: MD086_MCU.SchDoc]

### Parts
C15  Cap_F: 100nF  VDC_V: 50V  [0603]  (hidden comment: 885012206095)
C17  ValueDisplayed: 1nF  VDC_V: 100V  [FP-885012006085_0603-MFG]  (hidden comment: 885012006085)
C41  ValueDisplayed: 1nF  VDC_V: 100V  [FP-885012006085_0603-MFG]  (hidden comment: 885012006085)
C44  VDC_V: 50V  ValueDisplayed: 10pF  [0402]  (hidden comment: 885012005055)
C45  VDC_V: 50V  ValueDisplayed: 10pF  [0402]  (hidden comment: 885012005055)
C46  Cap_F: 100nF  VDC_V: 50V  [0603]  (hidden comment: 885012206095)
C49  VDC_V: 16V  Cap_F: 470nF  [FP-885012206050_0603-MFG]  (hidden comment: 885012206050)
C50  Cap_F: 100nF  VDC_V: 50V  [0603]  (hidden comment: 885012206095)
C51  ValueDisplayed: 10uF  VDC_V: 10V  [FP-875105240001_SMT_CAP_4MM3_4MM3-MFG]  (hidden comment: 875105240001)
C52  Cap_F: 100nF  VDC_V: 50V  [0603]  (hidden comment: 885012206095)
C53  Cap_F: 100nF  VDC_V: 50V  [0603]  (hidden comment: 885012206095)
C54  Cap_F: 100nF  VDC_V: 50V  [0603]  (hidden comment: 885012206095)
D3  value Super Red  [WL-SMCW_RED]  (hidden comment: 150060SS75000)
D5  150080VS75000  [WL-SMCW_Green_0805]  (value not drawn)
D6  150080VS75000  [WL-SMCW_Green_0805]  (value not drawn)
D8  150080VS75000  [WL-SMCW_Green_0805]  (value not drawn)
D10  150080VS75000  [WL-SMCW_Green_0805]  (value not drawn)
D11  150080VS75000  [WL-SMCW_Green_0805]  (value not drawn)
D14  150080VS75000  [WL-SMCW_Green_0805]  (value not drawn)
D15  150080VS75000  [WL-SMCW_Green_0805]  (value not drawn)
D18  150080VS75000  [WL-SMCW_Green_0805]  (value not drawn)
D19  150080VS75000  [WL-SMCW_Green_0805]  (value not drawn)
J6  61300311121  [WURTH_61300311121]  (value not drawn)
J7  61031621121  [FP-61031621121_HDR16-MFG]  (parts A,B of 2)
R9  value 10  [FP-560050310009_0402-MFG]  (hidden comment: 560050310009)
R18  ValueDisplayed: 47k  [0402]  (hidden comment: CRCW040247K0JNED)
R19  ValueDisplayed: 47k  [0402]  (hidden comment: CRCW040247K0JNED)
R30  ValueDisplayed: 10k  [0603L]  (hidden comment: RC0603JR-0710KL)
R31  ValueDisplayed: 10k  [0603L]  (hidden comment: RC0603JR-0710KL)
R32  ValueDisplayed: 10k  [0603L]  (hidden comment: RC0603JR-0710KL)
R37  value 10  [FP-560050310009_0402-MFG]  (hidden comment: 560050310009)
R39  ValueDisplayed: 10k  [0603L]  (hidden comment: RC0603JR-0710KL)
R40  ValueDisplayed: 10k  [0603L]  (hidden comment: RC0603JR-0710KL)
R41  ValueDisplayed: 10k  [0603L]  (hidden comment: RC0603JR-0710KL)
R43  ValueDisplayed: 4.99k  [0603L]  (hidden comment: CRCW06034K99FKEAC)
R45  ValueDisplayed: 330  [0603L]  (hidden comment: Resistor)
R47  ValueDisplayed: 330  [0603L]  (hidden comment: Resistor)
R48  ValueDisplayed: 330  [0603L]  (hidden comment: Resistor)
R49  ValueDisplayed: 330  [0603L]  (hidden comment: Resistor)
R51  ValueDisplayed: 10k  [0603L]  (hidden comment: RC0603JR-0710KL)
R52  ValueDisplayed: 10k  [0603L]  (hidden comment: RC0603JR-0710KL)
R53  ValueDisplayed: 10k  [0603L]  (hidden comment: RC0603JR-0710KL)
R54  ValueDisplayed: 10k  [0603L]  (hidden comment: RC0603JR-0710KL)
R80  ValueDisplayed: 330  [0603L]  (hidden comment: Resistor)
R83  ValueDisplayed: 330  [0603L]  (hidden comment: Resistor)
R84  ValueDisplayed: 330  [0603L]  (hidden comment: Resistor)
R87  ValueDisplayed: 330  [0603L]  (hidden comment: Resistor)
R88  ValueDisplayed: 330  [0603L]  (hidden comment: Resistor)
R90  ValueDisplayed: 470  [0402]  (hidden comment: RC0402FR-07470RL)
R91  ValueDisplayed: 470  [0402]  (hidden comment: RC0402FR-07470RL)
R92  ValueDisplayed: 470  [0402]  (hidden comment: RC0402FR-07470RL)
R93  ValueDisplayed: 470  [0402]  (hidden comment: RC0402FR-07470RL)
R94  ValueDisplayed: 4.70k  [0402]  (hidden comment: CRG0402F4K7)
R95  ValueDisplayed: 4.70k  [0402]  (hidden comment: CRG0402F4K7)
R96  ValueDisplayed: 4.70k  [0402]  (hidden comment: CRG0402F4K7)
S1  430481025816  [FP-430481025816_SMT_SW_6MM2_6MM2-MFG]
SH-J6  60900213421  [Wurth_60900213421]  (value not drawn)
SH-J7  60900213421  [Wurth_60900213421]  (value not drawn)
SH-J8  60900213421  [Wurth_60900213421]  (value not drawn)
SH-J9  60900213421  [Wurth_60900213421]  (value not drawn)
SH-J10  60900213421  [Wurth_60900213421]  (value not drawn)
SH-J11  60900213421  [Wurth_60900213421]  (value not drawn)
SH-J12  60900213421  [Wurth_60900213421]  (value not drawn)
SH-J19  60900213421  [Wurth_60900213421]  (value not drawn)
SH-J35  60900213421  [Wurth_60900213421]  (value not drawn)
TP19  TP_H0.45P0.75  [TP_H045P075]  (value not drawn)  (no BOM)
TP22  5002  [Keystone5002]  (value not drawn)
TP23  5002  [Keystone5002]  (value not drawn)
TP24  5002  [Keystone5002]  (value not drawn)
TP25  5002  [Keystone5002]  (value not drawn)
TP26  5002  [Keystone5002]  (value not drawn)
TP27  5002  [Keystone5002]  (value not drawn)
TP28  5002  [Keystone5002]  (value not drawn)
TP29  TP_H0.45P0.75  [TP_H045P075]  (value not drawn)  (no BOM)
TP30  TP_H0.45P0.75  [TP_H045P075]  (value not drawn)  (no BOM)
TP31  TP_H0.45P0.75  [TP_H045P075]  (value not drawn)  (no BOM)
TP32  TP_H0.45P0.75  [TP_H045P075]  (value not drawn)  (no BOM)
TP33  TP_H0.45P0.75  [TP_H045P075]  (value not drawn)  (no BOM)
TP34  TP_H0.45P0.75  [TP_H045P075]  (value not drawn)  (no BOM)
TP35  5011  [Keystone5011]  (value not drawn)
TP36  5003  [Keystone5003]  (value not drawn)
U1  MSP430F5338IPZ  [PZT0100A_N]
Y2  MS3V-T1R 32.768KHZ +/-20PPM 12.5PF  [XTAL_MS3V-T1R]  (value not drawn)

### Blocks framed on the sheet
MSP430: C15 C41 C44-C46 C49-C54 R9 R18 R37 TP29-TP36 U1 Y2

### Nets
GND: C15.2 C17.1 C41.1 C44.2 C45.2 C46.1 C49.1 C50.2 C51.1(CATHODE) C52.2 C53.2 C54.2 J7.1 J7.2 R30.2 R32.2 R43.1 R45.1 R47.1 R48.1 R49.1 R51.2 R52.2 R53.2 R80.1 R83.1 R84.1 R87.1 R88.1 S1.3 S1.4 TP35.1 U1.10(P5.1/VREF-/VEREF-) U1.12(AVSS1) U1.15(AVSS2) U1.26(DVSS1) U1.29(DVSS) U1.63(DVSS2) U1.76(VSSU) U1.83(AVSS3) U1.90(DVSS3) Y2.3(GND)
MCU_3V3: C46.2 C50.1 C51.2(ANODE) C52.1 C53.1 C54.1 D5.2(A) R9.2 R18.1 R19.2 R31.1 R37.1 R39.1 R40.1 R41.1 R54.1 TP36.1 U1.25(DVCC1) U1.64(DVCC2) U1.87(VBAT) U1.89(DVCC3)
VBAT: D6.2(A)
CHANNEL_0: D15.2(A) U1.50(P4.0/TB0.0)
CHANNEL_1: D19.2(A) U1.51(P4.1/TB0.1)
CHANNEL_2: D14.2(A) U1.52(P4.2/TB0.2)
CHANNEL_3: D18.2(A) U1.53(P4.3/TB0.3)
DRV_STATUS: D11.2(A) U1.35(P1.1/TA0.0)
FAULT_STATUS: D3.2(A) U1.36(P1.2/TA0.1)
GUI_STATUS: D10.2(A) U1.34(P1.0/TA0CLK/ACLK)
ID0: R39.2 R51.1 U1.43(P3.1/TA1.0)
ID1: R40.2 R52.1 U1.44(P3.2/TA1.1)
ID2: R41.2 R53.1 U1.45(P3.3/TA1.2)
ID3: R30.1 R54.2 U1.46(P3.4/TA2CLK/SMCLK)
ID4: R31.2 R32.1 U1.47(P3.5/TA2.0)
IN0: J7.3 TP22.1
IN0_MCU: R94.2 U1.69(P9.1)
IN1: J7.5 TP23.1
IN1_MCU: R95.2 U1.70(P9.2)
MCU_STATUS: D8.2(A) TP19.1 U1.37(P1.3/TA0.2)
MCU_UARTRXD: U1.61(P8.3/UCA1RXD/UCA1SOMI)
MCU_UARTTXD: U1.60(P8.2/UCA1TXD/UCA1SIMO)
nSCS: J7.15 TP28.1
nSCS_MCU: R90.2 U1.67(P8.7)
nSLEEP: J7.7 TP24.1
nSLEEP_MCU: R96.2 U1.71(P9.3)
PUSH: J6.3 U1.38(P1.4/TA0.3)
RST/SBWTDIO: C17.2 C41.2 J6.1 R18.2 R19.1 U1.96(~{RST}/NMI/SBWTDIO)
SCLK: J7.13 TP27.1
SCLK_MCU: R93.2 U1.62(P8.4/UCB1CLK/UCA1STE)
SDI: J7.11 TP26.1
SDI_MCU: R91.2 U1.65(P8.5/UCB1SIMO/UCB1SDA)
SDO: J7.9 TP25.1
SDO_MCU: R92.2 U1.66(P8.6/UCB1SOMI/UCB1SCL)
TST/SBWTCK: U1.91(TEST/SBWTCK)
VBAT_MON: U1.97(P6.0/CB0/A0)
NetC15_1: C15.1 R9.1 U1.9(P5.0/VREF+/VEREF+)
NetC44_1: C44.1 U1.14(XOUT) Y2.1
NetC45_1: C45.1 U1.13(XIN) Y2.2
NetC49_2: C49.2 U1.27(VCORE)
NetD3_1: D3.1(K) R80.2
NetD5_1: D5.1(K) R49.2
NetD6_1: D6.1(K) R43.2
NetD8_1: D8.1(K) R45.2
NetD10_1: D10.1(K) R47.2
NetD11_1: D11.1(K) R48.2
NetD14_1: D14.1(K) R83.2
NetD15_1: D15.1(K) R84.2
NetD18_1: D18.1(K) R87.2
NetD19_1: D19.1(K) R88.2
NetJ6_2: J6.2 S1.1 S1.2
NetJ7_4: J7.4 R94.1
NetJ7_6: J7.6 R95.1
NetJ7_8: J7.8 R96.1
NetJ7_10: J7.10 R92.1
NetJ7_12: J7.12 R91.1
NetJ7_14: J7.14 R93.1
NetJ7_16: J7.16 R90.1
NetR37_2: R37.2 U1.11(AVCC1)
NetTP29_1: TP29.1 U1.42(P3.0/TA1CLK/CBOUT)
NetTP30_1: TP30.1 U1.16(P5.6/ADC12CLK/DMAE0)
NetTP31_1: TP31.1 U1.88(P5.7/RTCCLK)
NetTP32_1: TP32.1 U1.19(P2.2/P2MAP2)
NetTP33_1: TP33.1 U1.20(P2.3/P2MAP3)
NetTP34_1: TP34.1 U1.21(P2.4/P2MAP4)

Not connected (* = marked no-connect by the designer): U1 1(P6.4/CB4/A4) 2(P6.5/CB5/A5) 3(P6.6/CB6/A6/DAC0) 4(P6.7/CB7/A7/DAC1) 5(P7.4/CB8/A12) 6(P7.5/CB9/A13) 7(P7.6/CB10/A14/DAC0) 8(P7.7/CB11/A15/DAC1) 17(P2.0/P2MAP0)* 18(P2.1/P2MAP1)* 22(P2.5/P2MAP5)* 23(P2.6/P2MAP6)* 24(P2.7/P2MAP7)* 28(P5.2) 30(DNC)* 31(P5.3) 32(P5.4) 33(P5.5) 39(P1.5/TA0.4) 40(P1.6/TA0.1) 41(P1.7/TA0.2) 48(P3.6/TA2.1) 49(P3.7/TA2.2) 54(P4.4/TB0.4) 55(P4.5/TB0.5) 56(P4.6/TB0.6) 57(P4.7/TB0OUTH/SVMOUT) 58(P8.0/TB0CLK) 59(P8.1/UCB1STE/UCA1CLK) 68(P9.0) 72(P9.4) 73(P9.5) 74(P9.6) 75(P9.7) 77(PU.0) 78(NC)* 79(PU.1) 80(LDOI)* 81(LDOO)* 82(NC)* 84(P7.2/XT2IN) 85(P7.3/XT2OUT) 86(VBAK)* 92(PJ.0/TDO) 93(PJ.1/TDI/TCLK) 94(PJ.2/TMS) 95(PJ.3/TCK) 98(P6.1/CB1/A1) 99(P6.2/CB2/A2) 100(P6.3/CB3/A3)

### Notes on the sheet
- LEDS
- Main Signal Header
- RST/PUSH Button
- ID Resistors
- (near SH-J35) DEFAULT
- (near SH-J35) PINS 1-2
- DRV81008-Q1
- Device
- ID3
- 0
- ID2
- ID1
- ID0
- MD075
- MD #
- DRV81080-Q1
- DRV81004-Q1
- 1
- MD086
- MD081
- DRV81242-Q1
- DRV81602-Q1
- DRV81620-Q1
- MD089
- MD091
- MD088
- (near S1) SELECT PUSH
- BUTTON FUNCTION
- PRE-PRODUCTION
- SILICON
- (near R30) ID4
- (near R30) 0
- By default the pushbutton will send a reset/restart signal to the MCU.
  If the jumper is in the "PUSH" position then the signal will go to a GPIO pin on the MCU to support custom firmware doing something else when the button is pressed.
- The resistors on the ID[3:0] nets inform the firmware which device ID variant is on this board
- PRODUCTION

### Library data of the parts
C15 C46 C50 C52-C54 = CMP-0006837-4: as C5 on sheet MD086_DRV81004
C17 C41 = CMP-0097311-1: as C12 on sheet MD086_DRV81004
C44 C45 = CMP-0006215-2: as C26 on sheet MD086_ezFET
C49 = CMP-0097608-1: as C29 on sheet MD086_ezFET
C51 = CMP-0097340-1: as C31 on sheet MD086_ezFET
D3 = CMP-0002893-1: as D1 on sheet MD086_ezFET
D5 D6 D8 D10 D11 D14 D15 D18 D19 = CMP-0002960-2: as D2 on sheet MD086_ezFET
J6 = CMP-0054796-4: as J1 on sheet MD086_DRV81004
J7 = CMP-0122702-1: Connector Header Surface Mount 16 position 0.100" (2.54mm); Manufacturer: Wurth; ContactFinish: Gold; Current_A: 3A; Row_Count: 2; Voltage_V: 250V; AEC Qualified: No; Conn Gender: Male; Conn Orientation: Straight; SizeZ_mm: 10mm
R9 R37 = CMP-0097401-1: as R64 on sheet MD086_ezFET
R18 R19 = CMP-0026935-3: as R57 on sheet MD086_ezFET
R30-R32 R39-R41 R51-R54 = CMP-0025886-5: as R98 on sheet MD086_DRV81004
R43 = CMP-0082533-1: RES, 4.99 k, 1%, 0.1 W, 0603; Manufacturer: Vishay-Dale; Value: 4.99k; Value_Code: 4k99; Power_W: 100mW; Value2: 0.1W; VDC_V: 75V; TempCo: 100 ppm/C; EIA_Code: E96; AEC Category: Q200; AEC Qualified: N; SizeAreaWB_mm2: 4.68; SizeX_mm: 1.6; SizeY_mm: 0.8; SizeZ_mm: 1; SizeArea_mm2: 1.28
R45 R47-R49 R80 R83 R84 R87 R88 = CMP-0025785-4: RES, 330, 5%, 0.1 W, AEC-Q200 Grade 0, 0603; PartNumber: CRCW0603330RJNEA; Manufacturer: Vishay-Dale; Value: 330; Value_Code: 330R; Power_W: 100mW; Value2: 0.1W; VDC_V: 75V; TempCo: 200 ppm/C; EIA_Code: E24; AEC Category: Q200; AEC Qualified: Y; AEC Grade: 0; SizeX_mm: 1.6; SizeY_mm: 0.8; SizeZ_mm: 1; SizeArea_mm2: 1.28
R90-R93 = CMP-0026736-1: RES, 470, 1%, 0.063 W, 0402; Manufacturer: Yageo America; Power_W: 63mW; TempCo: 100 ppm/C; Value_Code: 470R; U/M: EA; Value: 470; SizeX_mm: 1; SizeY_mm: 0.5; SizeZ_mm: 0.6; Value2: 0.063W; AEC Qualified: N; VDC_V: 50V; AEC Category: Q200
R94-R96 = CMP-0026631-1: RES, 4.70 k, 1%, 0.063 W, 0402; Manufacturer: TE Connectivity; Power_W: 63mW; TempCo: 100 ppm/C; Value_Code: 4k70; U/M: EA; Value: 4.70k; Res_ohm: 4.7k; SizeX_mm: 1; SizeY_mm: 0.5; SizeZ_mm: 0.6; Value2: 0.063W; AEC Qualified: N; AEC Category: Q200
S1 = CMP-0097347-1: Tactile Switch SPST-NO Top Actuated Surface Mount; Manufacturer: Wurth Electronics; VDC_V: 12V; Electromechanical Life: 1000000Cycles; SizeZ_mm: 2.7mm; Coil Resistance_ohm: 100mΩ; Operating Force: 160gf; AEC Qualified: No; Contact Current Rating: 50mA
SH-J6-SH-J12 SH-J19 SH-J35 = CMP-0003761-2: as SH-J34 on sheet MD086_DRV81004
TP19 TP29-TP34 = CMP-0003719-1: Testpoint; Manufacturer: Texas Instruments; CompType: Pad
TP22-TP28 = CMP-0055139-2: Test Point, Miniature, White, TH; Manufacturer: Keystone Electronics; ContactFinish: Silver; Green_REACh: Passed; CT: TRUE; Green_Lifecycle: Active; CNHeader: FALSE
TP35 = CMP-0055148-2: as TP1 on sheet MD086_DRV81004
TP36 = CMP-0055140-2: Test Point, Miniature, Orange, TH; Manufacturer: Keystone Electronics; CNHeader: FALSE; Green_Lifecycle: Active; Green_REACh: Passed; ContactFinish: Silver; CT: TRUE
U1 = CMP-0038879-1: 20 MHz Mixed Signal Microcontroller with 256 KB Flash, 18432 B SRAM and 74 GPIOs, -40 to 85 degC, 100-pin QFP (PZ), Green (RoHS & no Sb/Br); Manufacturer: Texas Instruments; Flash(KB): 256; USCI_B (I2C & SPI): 2; ADC Channels: 16; Comparators: Yes; Frequency(MHz): 20; DMA: 3; SRAM(B): 18432; Multiplier: 32x32; GPIO: 74; Timers - 16-bit: 4; SubFamily: 5 Series; ADC: 12-bit SAR
Y2 = CMP-0004566-4: Crystal, 32.768 kHz, 12.5pF, SMD; Manufacturer: Micro Crystal AG; PartNumber: MS3V-T1R-32.768KHZ-12.5PF-20PPM-TA-QC; TaMin_C: -40°C; TaMax_C: 85°C; AEC Category: Q200; AEC Qualified: N; Frequency Tolerance: 20 ppm

## Sheet MD086_Hardware.SchDoc
size 431 x 279 mm; Date: Not shown in title block; ApprovedBy: Not shown in title block; CheckedBy: Not shown in title block; Author: Not shown in title block; CompanyName: Not shown in title block; DrawnBy: David Medis; Engineer: Not shown in title block; Organization: Not shown in title block; Address1: Not shown in title block; Address2: Not shown in title block; Address3: Not shown in title block; Address4: Not shown in title block; DocumentNumber: 4; Revision: Use project parameter SCH_Rev; SheetNumber: 4; SheetTotal: 4; PageSetup: Record=PageOptions¦CenterHorizontal=True¦CenterVertical=True¦PrintScale=1.00¦XCorrection=1.00¦YCorrection=1.00¦PrintKind=0¦BorderSize=5000000¦LeftOffset=0¦BottomOffset=0¦Orientation=2¦PaperLength=1000¦PaperWidth=1000¦Scale=100¦PaperSource=15¦PrintQuality=600¦MediaType=1¦DitherType=10¦PaperKind=Letter¦PrintScaleMode=1
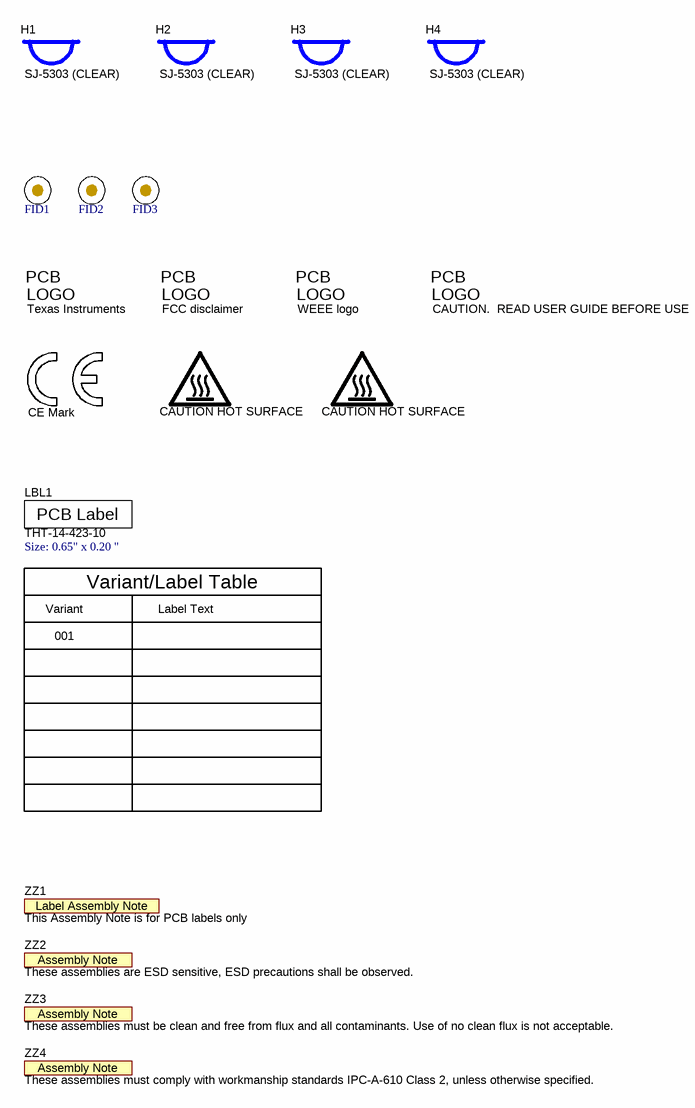
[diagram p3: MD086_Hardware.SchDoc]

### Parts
FID1  Fiducial  [Fiducial10-20]  (value not drawn)  (no BOM)
FID2  Fiducial  [Fiducial10-20]  (value not drawn)  (no BOM)
FID3  Fiducial  [Fiducial10-20]  (value not drawn)  (no BOM)
H1  SJ-5303 (CLEAR)  [Bumpon_SJ5003Transparent]
H2  SJ-5303 (CLEAR)  [Bumpon_SJ5003Transparent]
H3  SJ-5303 (CLEAR)  [Bumpon_SJ5003Transparent]
H4  SJ-5303 (CLEAR)  [Bumpon_SJ5003Transparent]
LBL1  THT-14-423-10  Note: Size: 0.65" x 0.20 "  [Label_650x200]
Logo1  CE Mark  [CE_Mark_5mm]  (no BOM)
Logo2  Texas Instruments  [TI_Stacked_Overlay_Medium]  (no BOM)
Logo3  FCC disclaimer  [FCC_disclaimer]  (no BOM)
Logo4  WEEE logo  [WEEE_Minimum]  (no BOM)
Logo5  CAUTION.  READ USER GUIDE BEFORE USE  [IEC_Caution_Small]  (no BOM)
LOGO6  CAUTION HOT SURFACE  [IEC_HotSurface_Small]  (no BOM)
LOGO7  CAUTION HOT SURFACE  [IEC_HotSurface_Small]  (no BOM)
ZZ1  This Assembly Note is for PCB labels only  [AssemblyNoteLabel]  (no BOM)
ZZ2  These assemblies are ESD sensitive, ESD precautions shall be observed.  [AssemblyNote]  (no BOM)
ZZ3  These assemblies must be clean and free from flux and all contaminants. Use of no clean flux is not acceptable.  [AssemblyNote]  (no BOM)
ZZ4  These assemblies must comply with workmanship standards IPC-A-610 Class 2, unless otherwise specified.  [AssemblyNote]  (no BOM)

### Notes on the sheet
- Variant/Label Table
- Variant
- 001
- Label Text

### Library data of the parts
FID1-FID3 = CMP-0077181-1: Fiducial mark.  There is nothing to buy or mount.
H1-H4 = CMP-0003620-1: Bumpon, Hemisphere, 0.44 X 0.20, Clear; Manufacturer: 3M
LBL1 = CMP-0003625-1: Thermal Transfer Printable Labels, 0.650" W x 0.200" H - 10,000 per roll; Manufacturer: Brady
Logo1 = CMP-0074844-2: Manufacturer: Texas Instruments; SymbolCreator: a0412235; AEC Category: Q200; CompType: IC
Logo2 = CMP-0074838-1: Texas Instrument Corporate Signature; SymbolCreator: a0412235; Lib Reference: TI_Logo
Logo3 = CMP-0074847-1: FCC_disclaimer
Logo4 = CMP-0074769-4: Manufacturer: Texas Instruments; CompType: IC; AEC Category: Q200
Logo5 = CMP-0074836-1: IEC 61010-1 Caution Warning; SymbolCreator: a0412235; Lib Reference: IEC_Caution
LOGO6 LOGO7 = CMP-0074837-2: IEC 61010-1 Hot Surface Warning; Manufacturer: Texas Instruments; SymbolCreator: a0412235; CompType: IC; AEC Category: Q200
ZZ1 = CMP-0003616-3
ZZ2 = CMP-0077236-1
ZZ3 = CMP-0077237-1
ZZ4 = CMP-0077238-1

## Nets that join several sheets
GND: MD086_DRV81004 (40 pins), MD086_ezFET (45 pins), MD086_MCU (42 pins)
MCU_3V3: MD086_DRV81004 (J1.3), MD086_ezFET (J10.10), MD086_MCU (21 pins)
VBAT: MD086_DRV81004 (12 pins), MD086_MCU (D6.2)
IN0: MD086_DRV81004 (U5.13), MD086_MCU (J7.3 TP22.1)
IN1: MD086_DRV81004 (U5.12), MD086_MCU (J7.5 TP23.1)
MCU_UARTRXD: MD086_ezFET (J10.8), MD086_MCU (U1.61)
MCU_UARTTXD: MD086_ezFET (J10.6), MD086_MCU (U1.60)
nSCS: MD086_DRV81004 (U5.1), MD086_MCU (J7.15 TP28.1)
nSLEEP: MD086_DRV81004 (U5.11), MD086_MCU (J7.7 TP24.1)
RST/SBWTDIO: MD086_ezFET (J10.4), MD086_MCU (6 pins)
SCLK: MD086_DRV81004 (U5.2), MD086_MCU (J7.13 TP27.1)
SDI: MD086_DRV81004 (U5.3), MD086_MCU (J7.11 TP26.1)
SDO: MD086_DRV81004 (U5.4), MD086_MCU (J7.9 TP25.1)
TST/SBWTCK: MD086_ezFET (J10.2), MD086_MCU (U1.91)
VBAT_MON: MD086_DRV81004 (D20.1 R97.1 R98.1), MD086_MCU (U1.97)

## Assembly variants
001: not fitted C55 C56 C57 C58 C59 C60 C61 C62 R32 R40 R41 R51 R54 R62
